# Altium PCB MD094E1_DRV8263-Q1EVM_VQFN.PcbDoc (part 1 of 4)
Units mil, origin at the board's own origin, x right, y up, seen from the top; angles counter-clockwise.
Board outline 3224.41 x 4078.74 mil, 4 copper layers (Top Layer, Signal Layer 1, Signal Layer 2, Bottom Layer), stack 61.2 mil thick; 223 components, 125 nets, 631 pads, 683 vias.
Unrouted connection lines stored in the file: 74.
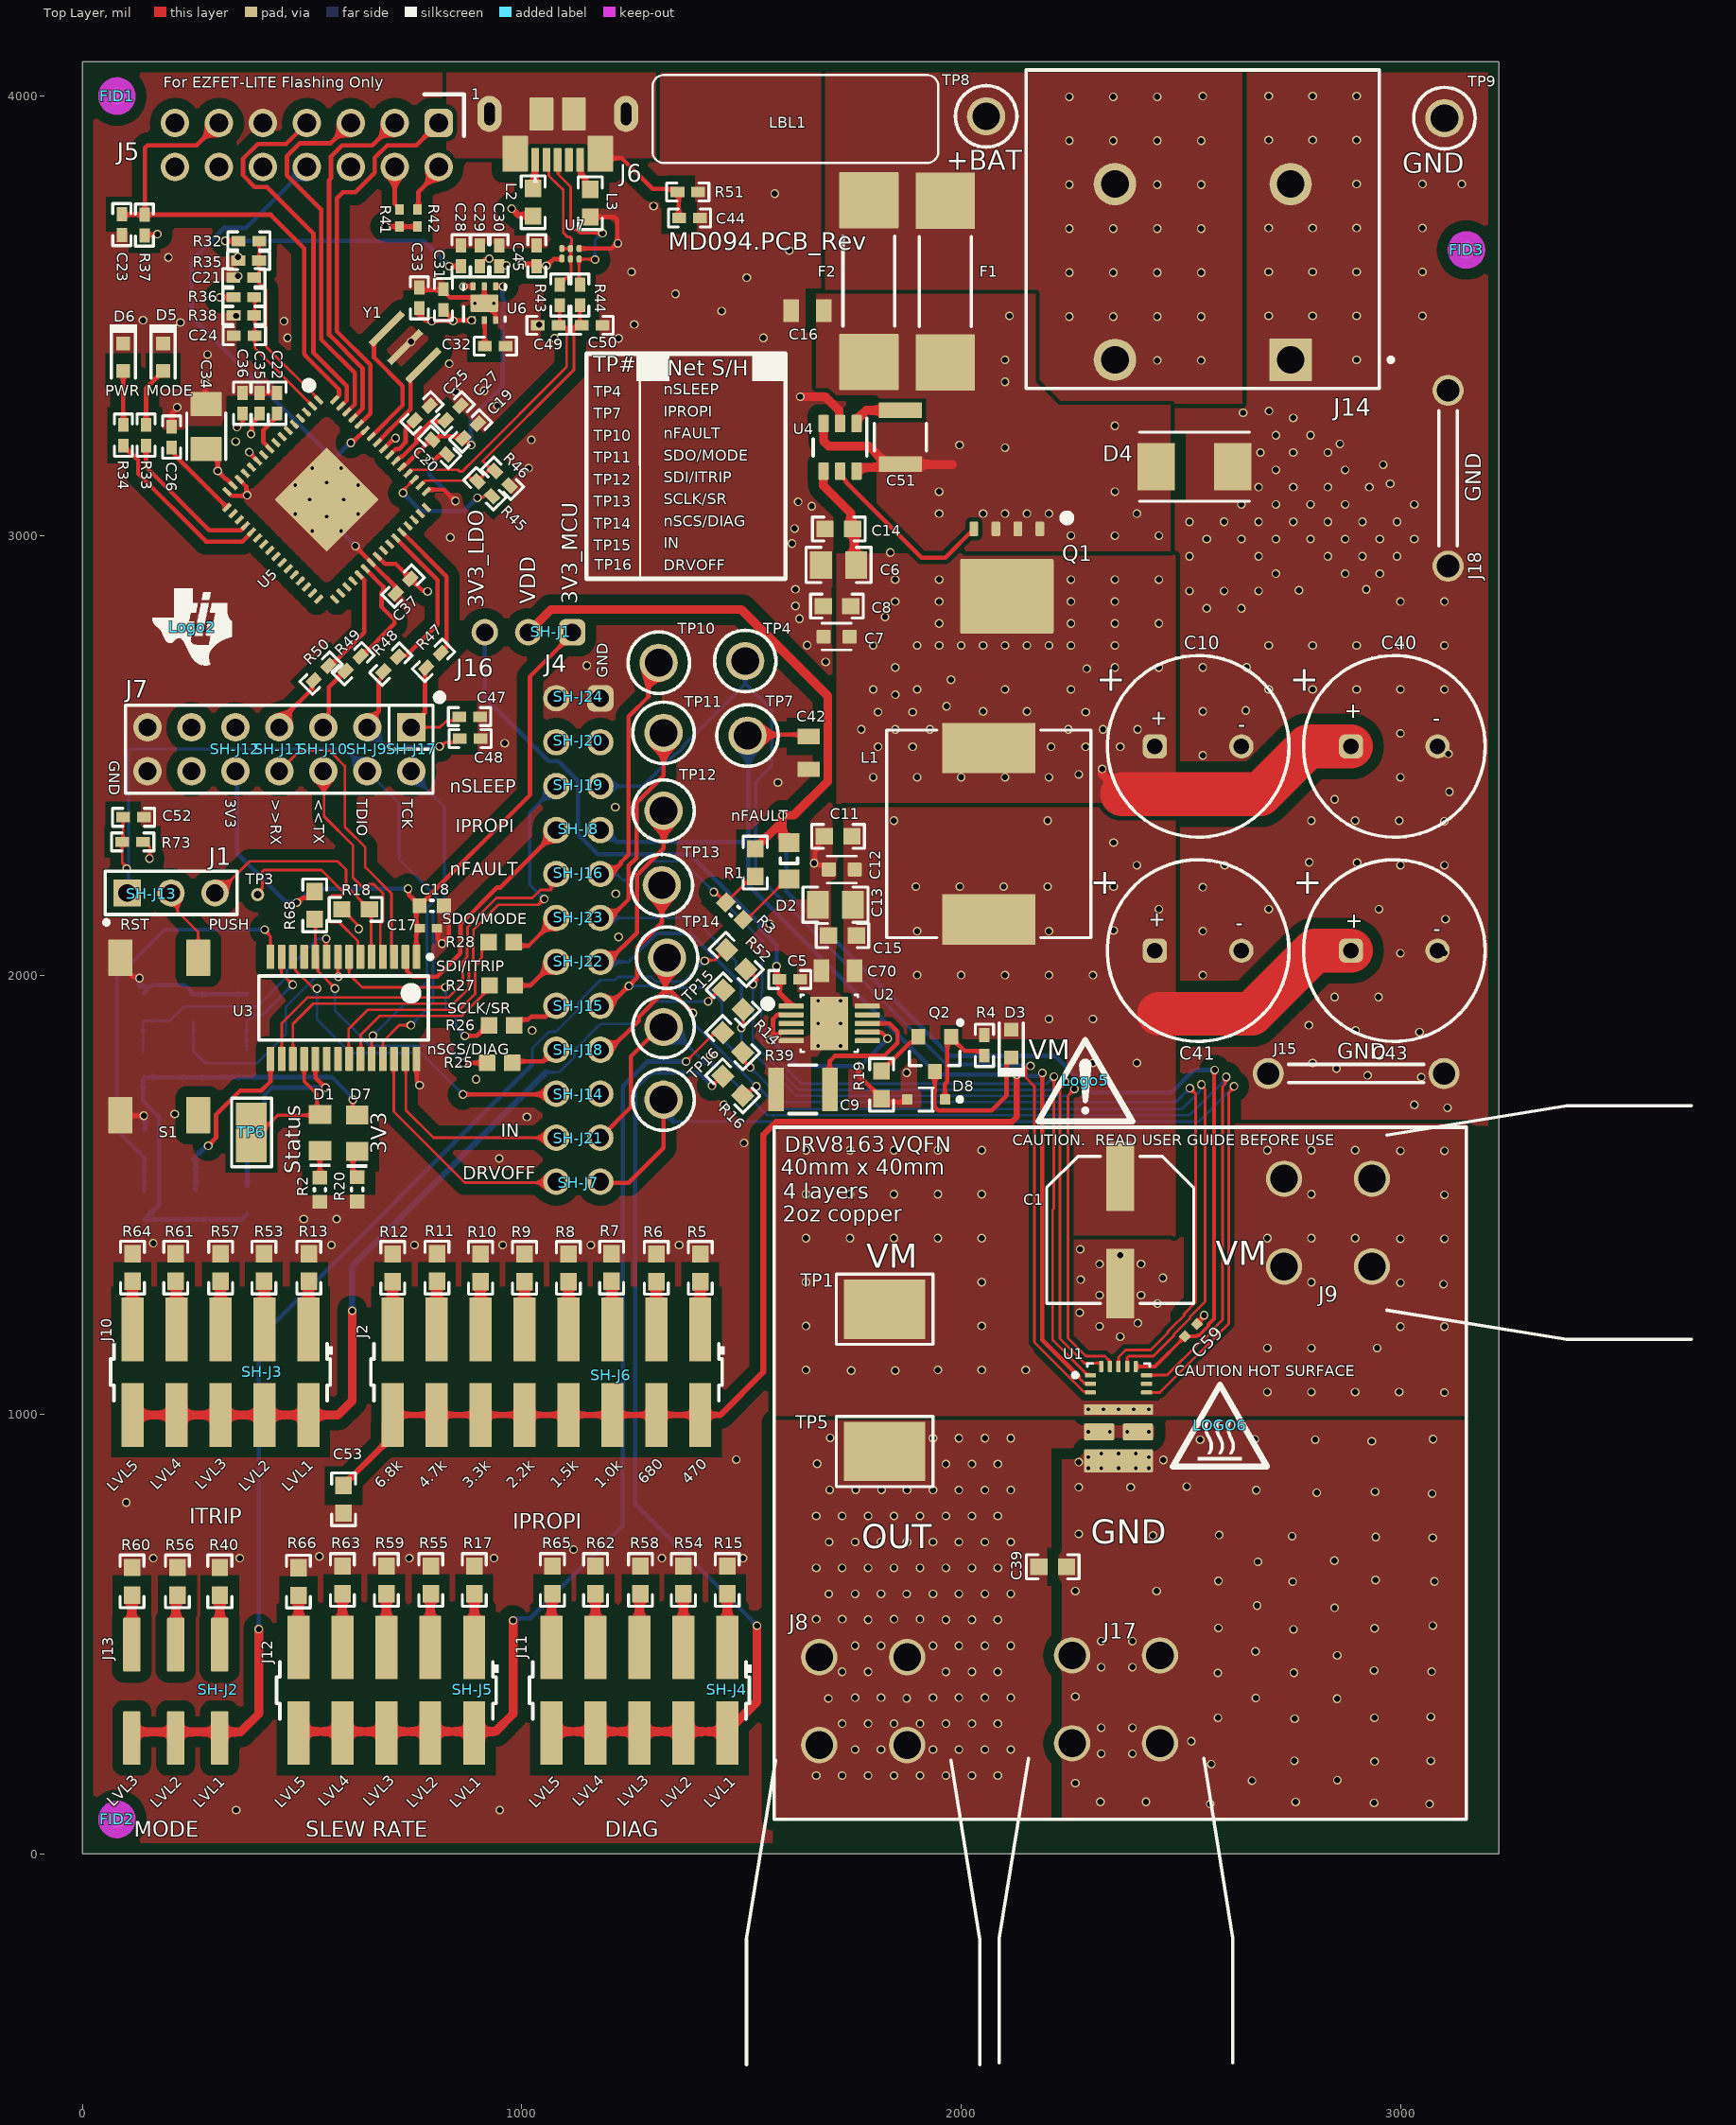
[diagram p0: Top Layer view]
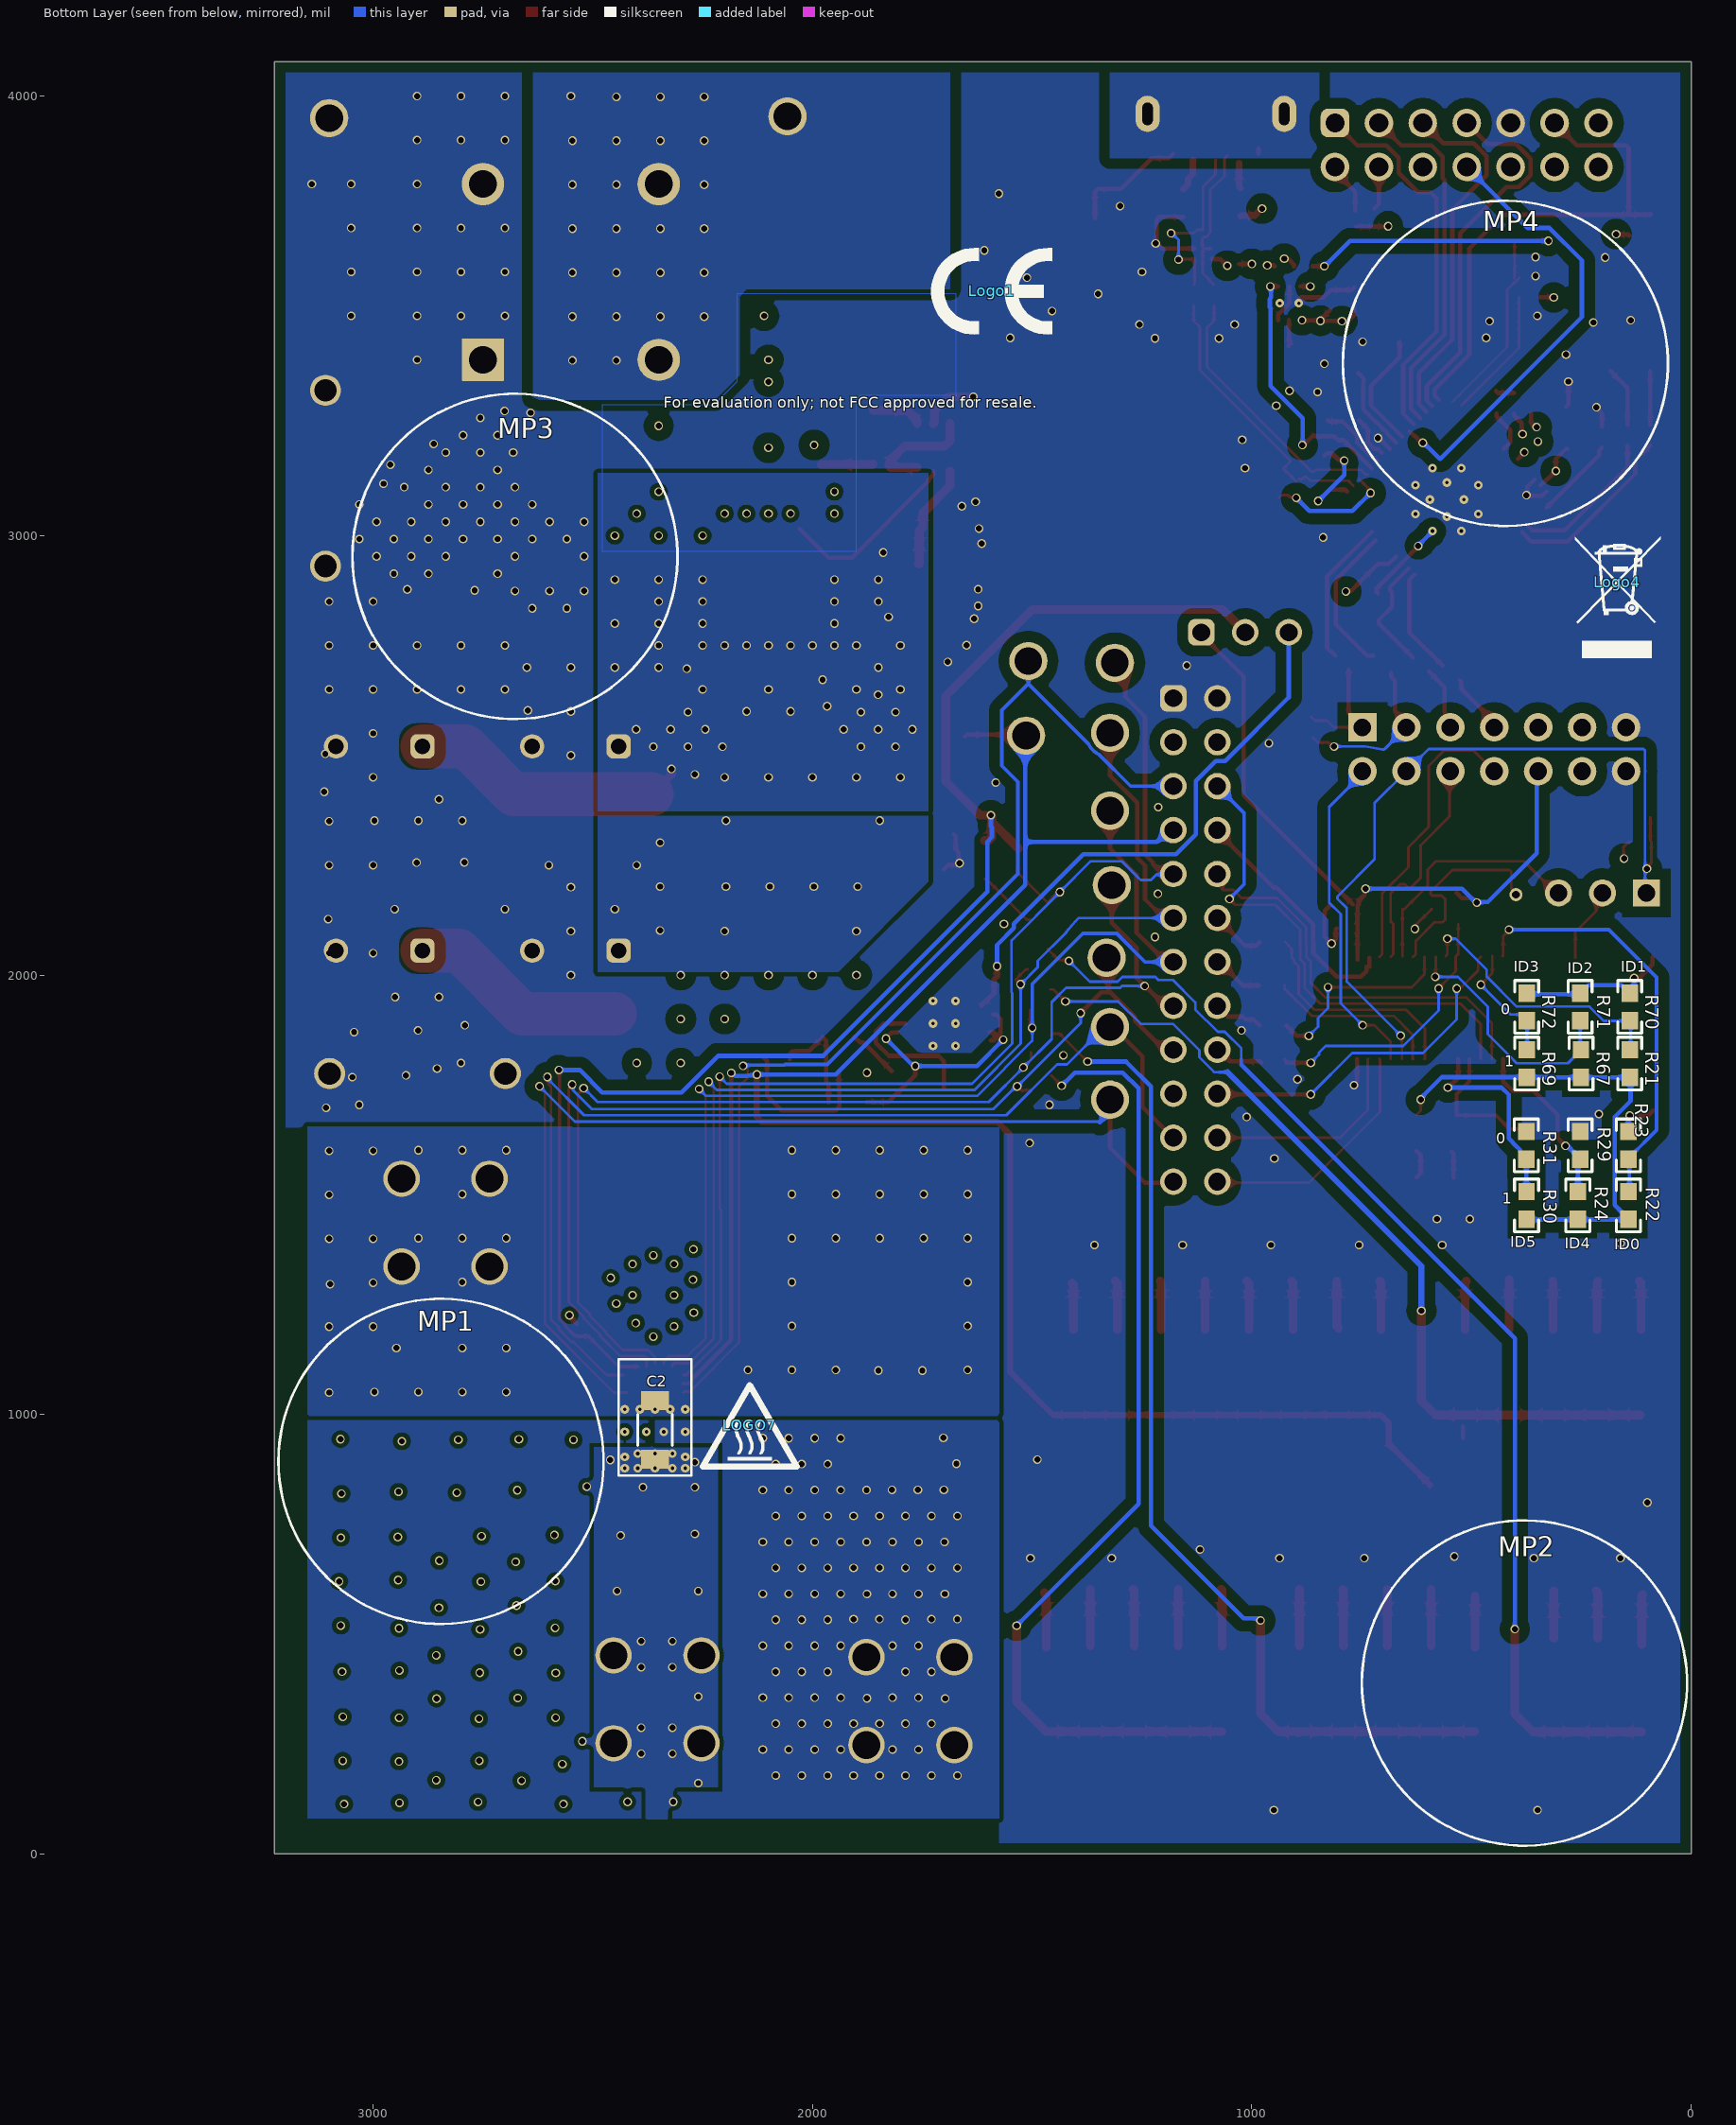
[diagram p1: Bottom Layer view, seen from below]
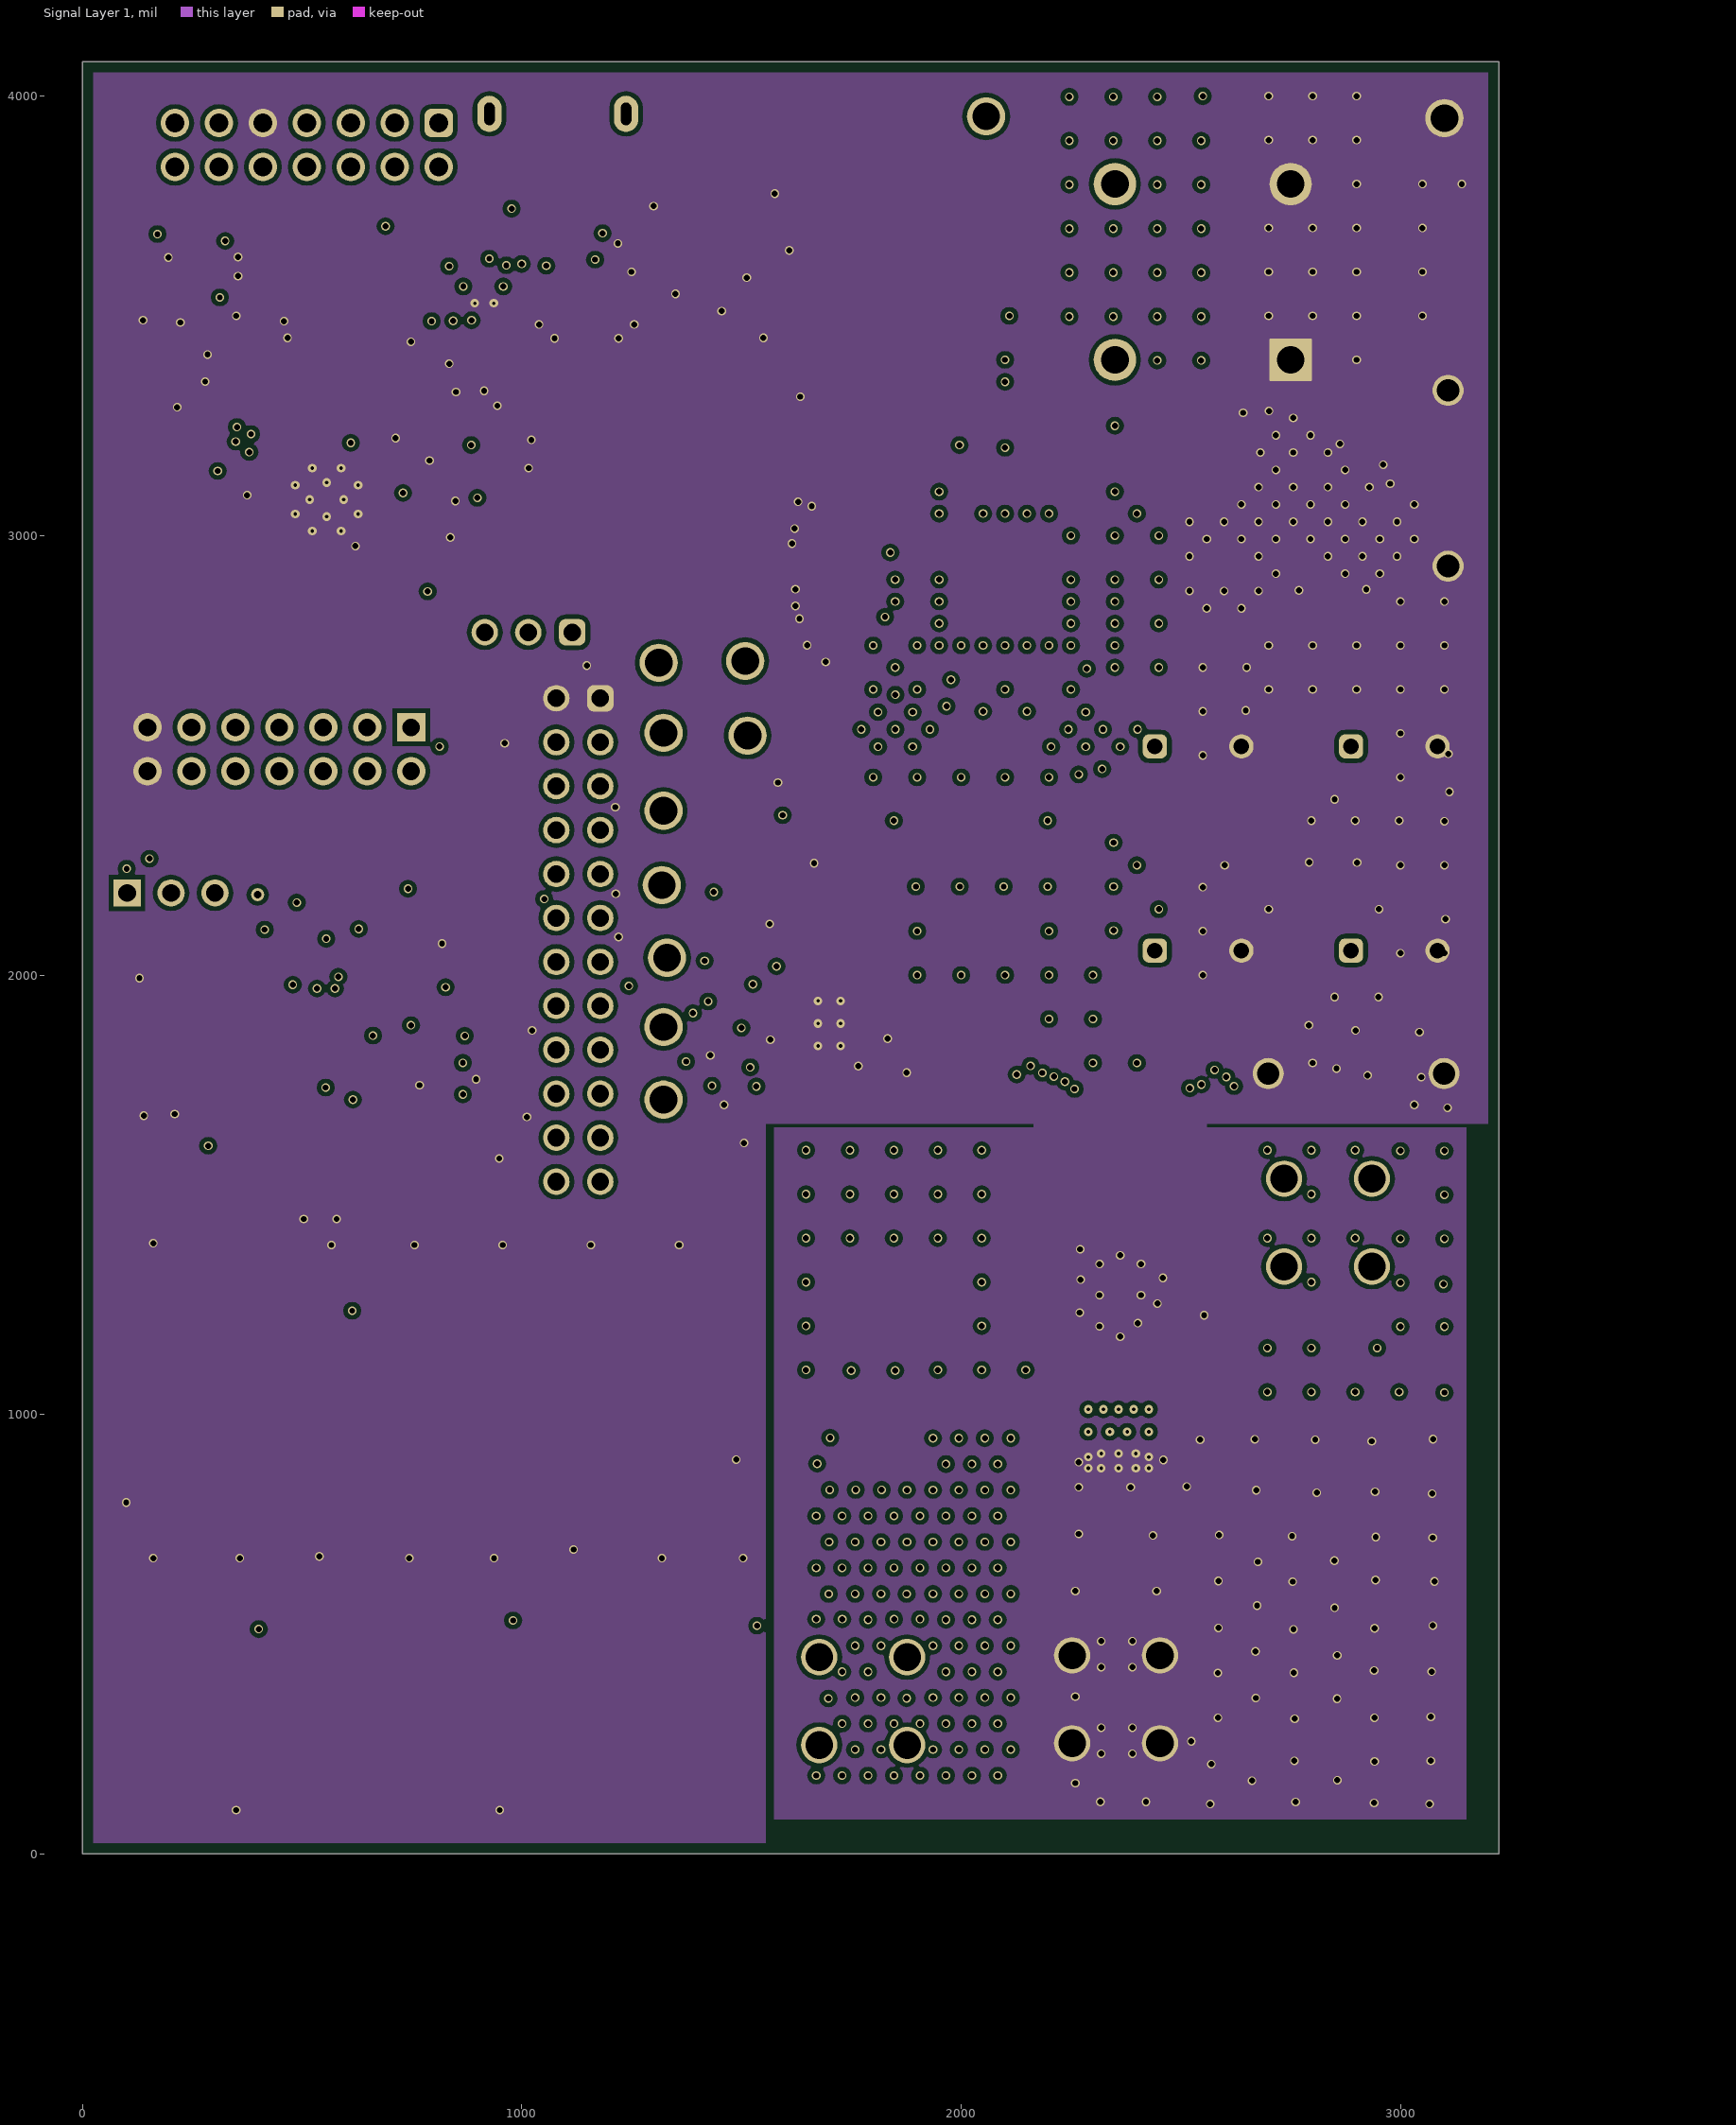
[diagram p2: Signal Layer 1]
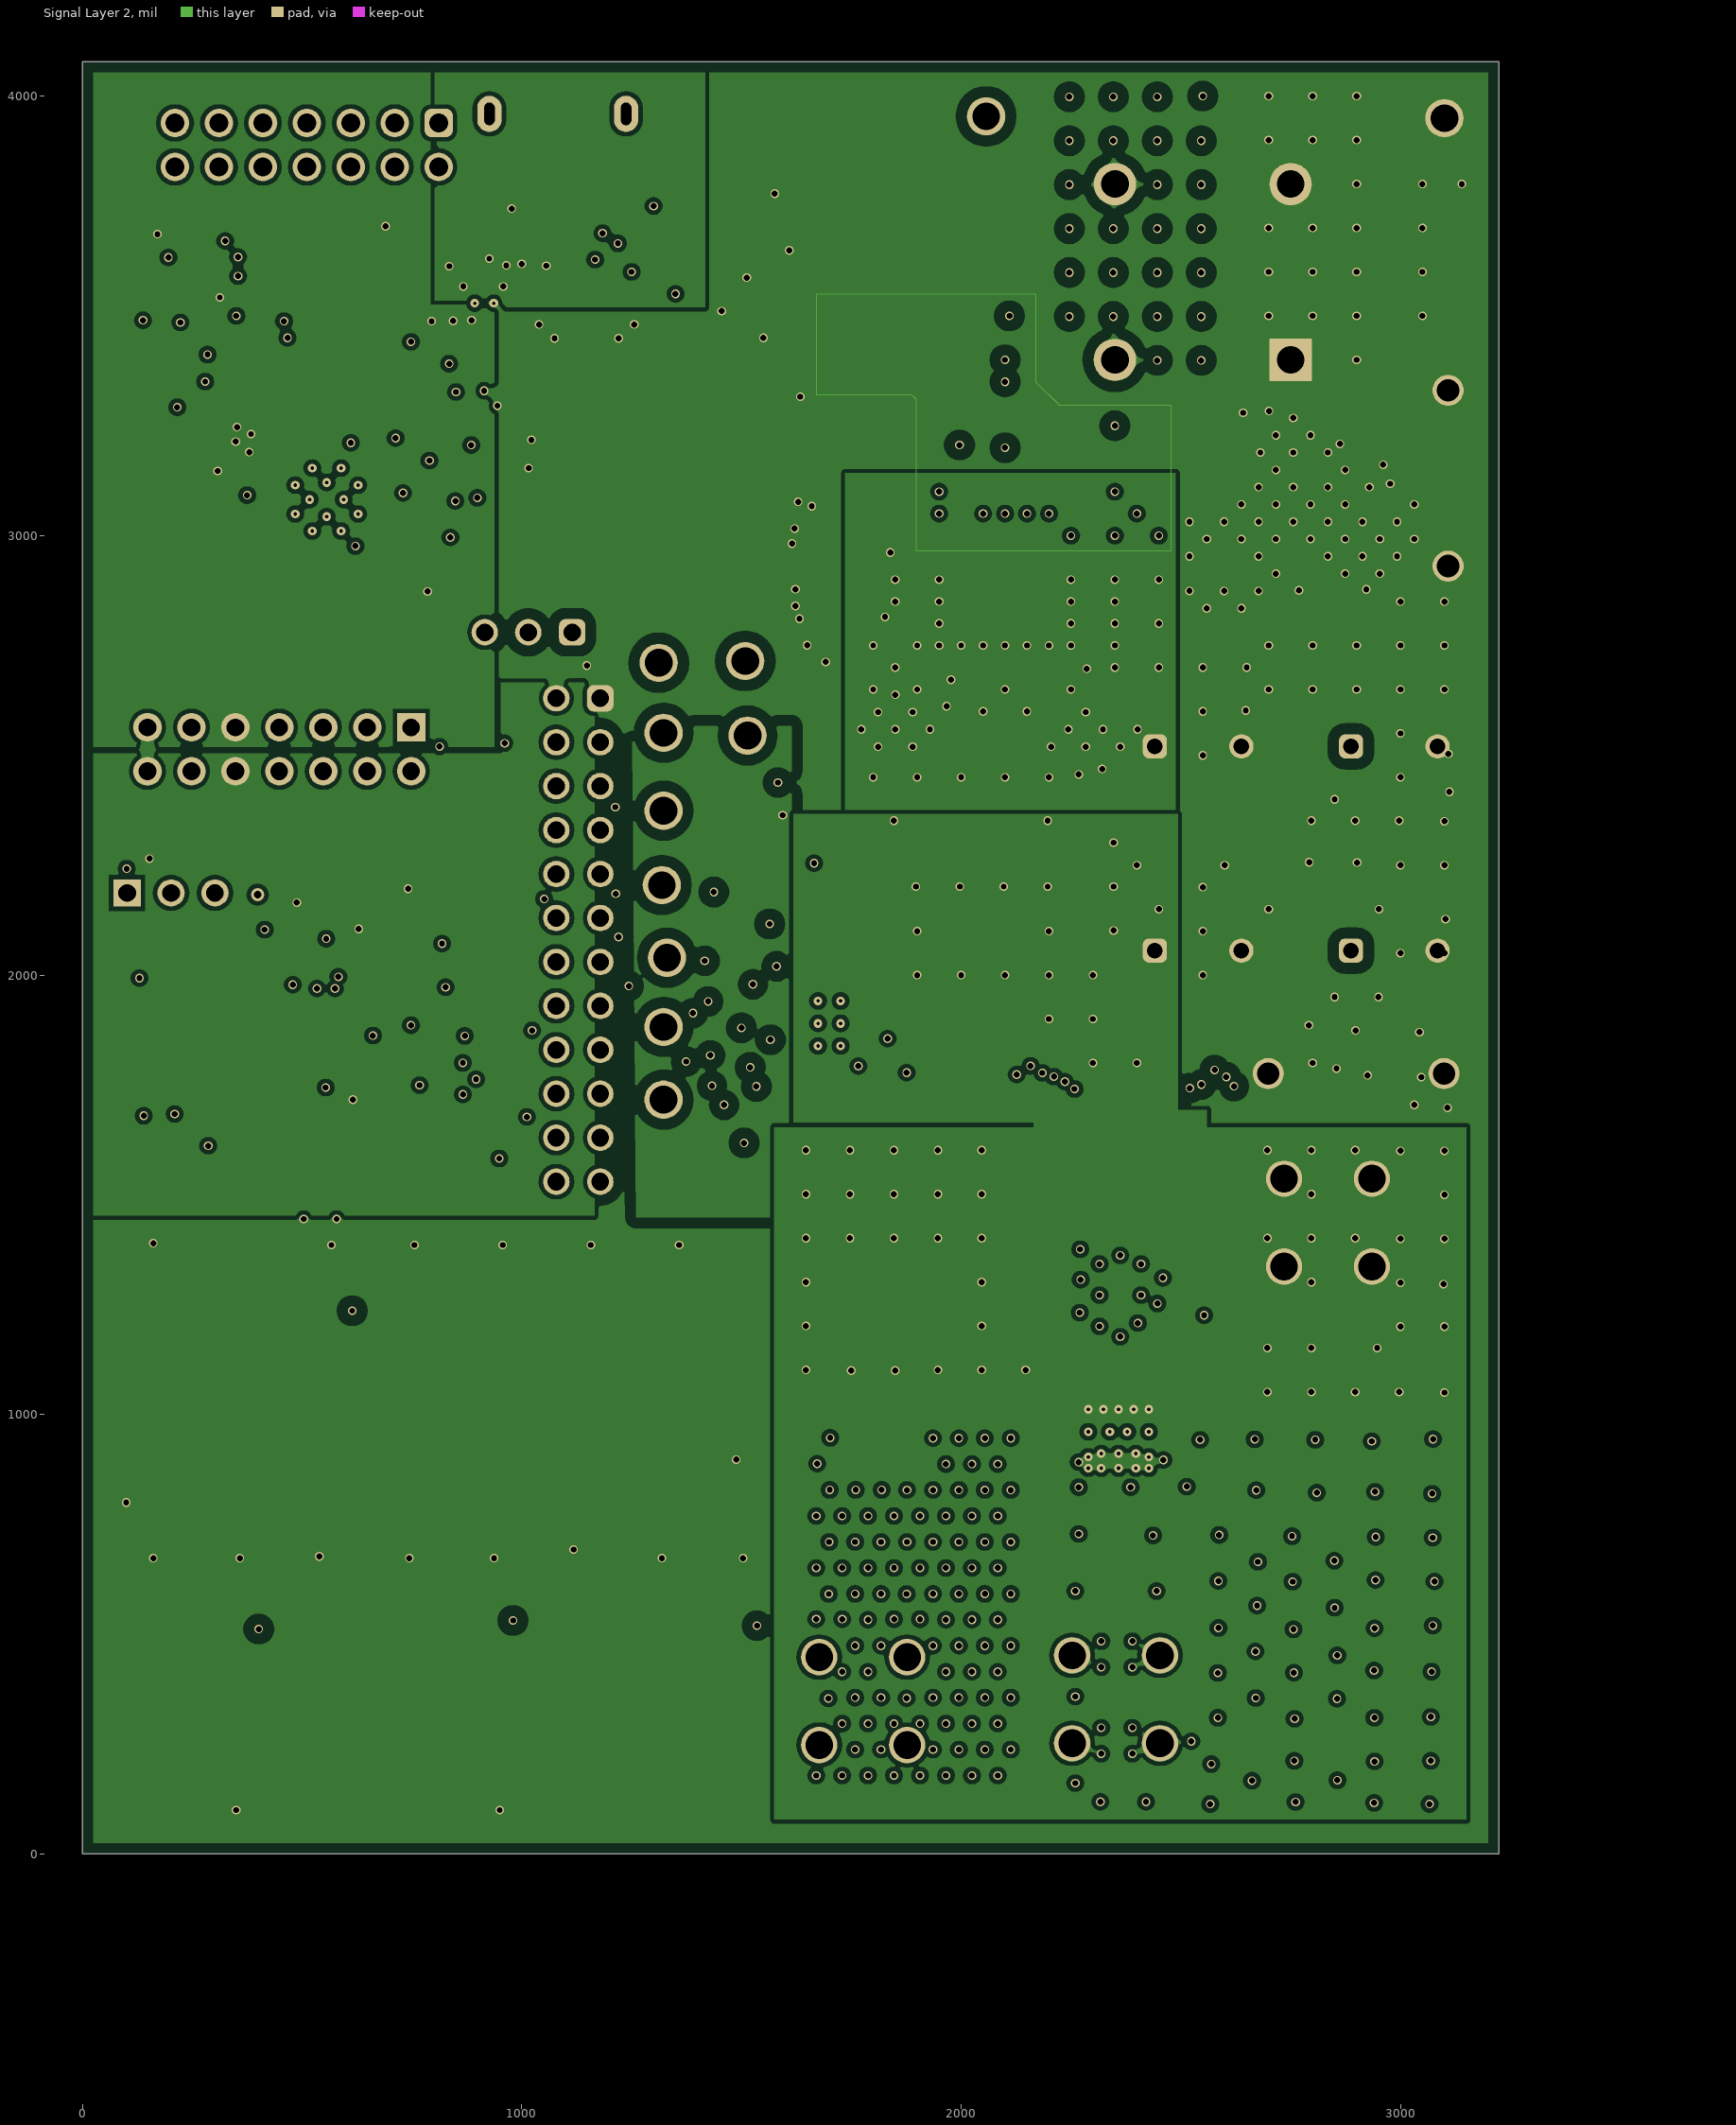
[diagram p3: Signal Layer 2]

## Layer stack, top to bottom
Top Solder: solder mask 0.4, Solder Resist, Dk 3.5
Top Layer: signal copper 2.8
Dielectric 1: prepreg 11.4, FR4 370, Dk 4.2
Signal Layer 1: signal copper 1.4
Dielectric 2: core 30, FR4 370, Dk 4.2
Signal Layer 2: signal copper 1.4
Dielectric 3: prepreg 11.4, FR4 370, Dk 4.2
Bottom Layer: signal copper 2.8
Bottom Solder: solder mask 0.4, Solder Resist, Dk 3.5

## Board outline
0,0 3224.41,0 3224.41,4078.74 0,4078.74

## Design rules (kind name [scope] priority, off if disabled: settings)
AcuteAngle [All] p1: minimum=4.50000000000000E+0001 checktracksonly=FALSE
AssemblyTestPointUsage [All] p1: valid=2
BoardOutlineClearance BoardOutlineClearance_MountingHoles [OnCopper and InComponentClass('Mounting Holes')] p1: gap=39.37 ignorepadtopadclearanceinfootprint=FALSE
BoardOutlineClearance BoardOutlineClearance_Poly [OnCopper and IsPoly] p2: gap=25 ignorepadtopadclearanceinfootprint=FALSE
BoardOutlineClearance [OnCopper and Not InComponentClass('Logo') and not InComponentClass('FiducialMark') and not InRegion(1000,500,4000,800) and not InPoly] p3: gap=75 ignorepadtopadclearanceinfootprint=FALSE
Clearance Clearance_89 [InNamedPolygon('TOP_LAYER_OUT1_P119')] p1: gap=10 ignorepadtopadclearanceinfootprint=TRUE except(0: Arc-Hole Track-Hole SMDPad-Hole THPad-Hole Via-Hole Fill-Hole Poly-Hole Region-Hole Text-Hole)
Clearance Clearance_88 [InNamedPolygon('TOP_LAYER_NONET_P-001')] p2: gap=10 ignorepadtopadclearanceinfootprint=TRUE except(0: Arc-Hole Track-Hole SMDPad-Hole THPad-Hole Via-Hole Fill-Hole Poly-Hole Region-Hole Text-Hole)
Clearance Clearance_87 [InNamedPolygon('TOP_LAYER_NONET_P-001')] p3: gap=10 ignorepadtopadclearanceinfootprint=TRUE except(0: Arc-Hole Track-Hole SMDPad-Hole THPad-Hole Via-Hole Fill-Hole Poly-Hole Region-Hole Text-Hole)
Clearance Clearance_86 [InNamedPolygon('TOP_LAYER_GND_P227')] p4: gap=10 ignorepadtopadclearanceinfootprint=TRUE except(0: Arc-Hole Track-Hole SMDPad-Hole THPad-Hole Via-Hole Fill-Hole Poly-Hole Region-Hole Text-Hole)
Clearance Clearance_85 [InNamedPolygon('TOP_LAYER_VM_P229')] p5: gap=10 ignorepadtopadclearanceinfootprint=TRUE except(0: Arc-Hole Track-Hole SMDPad-Hole THPad-Hole Via-Hole Fill-Hole Poly-Hole Region-Hole Text-Hole)
Clearance Clearance_84 [InNamedPolygon('TOP_LAYER_GND_P129')] p6: gap=10 ignorepadtopadclearanceinfootprint=TRUE except(0: Arc-Hole Track-Hole SMDPad-Hole THPad-Hole Via-Hole Fill-Hole Poly-Hole Region-Hole Text-Hole)
Clearance Clearance_83 [InNamedPolygon('TOP_LAYER_OUT1_P221')] p7: gap=3.94 ignorepadtopadclearanceinfootprint=TRUE except(0: Arc-Hole Track-Hole SMDPad-Hole THPad-Hole Via-Hole Fill-Hole Poly-Hole Region-Hole Text-Hole)
Clearance Clearance_82 [InNamedPolygon('TOP_LAYER_OUT1_P119')] p8: gap=10 ignorepadtopadclearanceinfootprint=TRUE except(0: Arc-Hole Track-Hole SMDPad-Hole THPad-Hole Via-Hole Fill-Hole Poly-Hole Region-Hole Text-Hole)
Clearance Clearance_81 [InNamedPolygon('TOP_LAYER_OUT1_P119')] p9: gap=10 ignorepadtopadclearanceinfootprint=TRUE except(0: Arc-Hole Track-Hole SMDPad-Hole THPad-Hole Via-Hole Fill-Hole Poly-Hole Region-Hole Text-Hole)
Clearance Clearance_80 [InNamedPolygon('TOP_LAYER_OUT1_P119')] p10: gap=10 ignorepadtopadclearanceinfootprint=TRUE except(0: Arc-Hole Track-Hole SMDPad-Hole THPad-Hole Via-Hole Fill-Hole Poly-Hole Region-Hole Text-Hole)
Clearance Clearance_79 [InNamedPolygon('TOP_LAYER_OUT1_P221')] p11: gap=10 ignorepadtopadclearanceinfootprint=TRUE except(0: Arc-Hole Track-Hole SMDPad-Hole THPad-Hole Via-Hole Fill-Hole Poly-Hole Region-Hole Text-Hole)
Clearance Clearance_78 [InNamedPolygon('TOP_LAYER_GND_P129')] p12: gap=10 ignorepadtopadclearanceinfootprint=TRUE except(0: Arc-Hole Track-Hole SMDPad-Hole THPad-Hole Via-Hole Fill-Hole Poly-Hole Region-Hole Text-Hole)
Clearance Clearance_77 [InNamedPolygon('TOP_LAYER_OUT2_P125')] p13: gap=10 ignorepadtopadclearanceinfootprint=TRUE except(0: Arc-Hole Track-Hole SMDPad-Hole THPad-Hole Via-Hole Fill-Hole Poly-Hole Region-Hole Text-Hole)
Clearance Clearance_76 [InNamedPolygon('TOP_LAYER_OUT1_P119')] p14: gap=10 ignorepadtopadclearanceinfootprint=TRUE except(0: Arc-Hole Track-Hole SMDPad-Hole THPad-Hole Via-Hole Fill-Hole Poly-Hole Region-Hole Text-Hole)
Clearance Clearance_75 [InNamedPolygon('TOP_LAYER_VM_P085')] p15: gap=10 ignorepadtopadclearanceinfootprint=TRUE except(0: Arc-Hole Track-Hole SMDPad-Hole THPad-Hole Via-Hole Fill-Hole Poly-Hole Region-Hole Text-Hole)
Clearance Clearance_74 [InNamedPolygon('TOP_LAYER_GND_P121')] p16: gap=10 ignorepadtopadclearanceinfootprint=TRUE except(0: Arc-Hole Track-Hole SMDPad-Hole THPad-Hole Via-Hole Fill-Hole Poly-Hole Region-Hole Text-Hole)
Clearance Clearance_73 [InNamedPolygon('TOP_LAYER_OUT2_P125') Or  InNamedPolygon('TOP_LAYER_OUT1_P119')] p17: gap=1.97 ignorepadtopadclearanceinfootprint=TRUE except(0: Arc-Hole Track-Hole SMDPad-Hole THPad-Hole Via-Hole Fill-Hole Poly-Hole Region-Hole Text-Hole)
Clearance Clearance_72 [InNamedPolygon('TOP_LAYER_OUT1_P119') Or  InNamedPolygon('TOP_LAYER_OUT2_P125')] p18: gap=3.94 ignorepadtopadclearanceinfootprint=TRUE except(0: Arc-Hole Track-Hole SMDPad-Hole THPad-Hole Via-Hole Fill-Hole Poly-Hole Region-Hole Text-Hole)
Clearance Clearance_71 [InNamedPolygon('TOP_LAYER_OUT1_P119')] p19: gap=10 ignorepadtopadclearanceinfootprint=TRUE except(0: Arc-Hole Track-Hole SMDPad-Hole THPad-Hole Via-Hole Fill-Hole Poly-Hole Region-Hole Text-Hole)
Clearance Clearance_70 [InNamedPolygon('TOP_LAYER_OUT2_P125')] p20: gap=10 ignorepadtopadclearanceinfootprint=TRUE except(0: Arc-Hole Track-Hole SMDPad-Hole THPad-Hole Via-Hole Fill-Hole Poly-Hole Region-Hole Text-Hole)
Clearance Clearance_69 [InNamedPolygon('TOP_LAYER_OUT1_P119')] p21: gap=3.94 ignorepadtopadclearanceinfootprint=TRUE except(0: Arc-Hole Track-Hole SMDPad-Hole THPad-Hole Via-Hole Fill-Hole Poly-Hole Region-Hole Text-Hole)
Clearance Clearance_68 [InNamedPolygon('TOP_LAYER_OUT2_P125')] p22: gap=3.94 ignorepadtopadclearanceinfootprint=TRUE except(0: Arc-Hole Track-Hole SMDPad-Hole THPad-Hole Via-Hole Fill-Hole Poly-Hole Region-Hole Text-Hole)
Clearance Clearance_67 [InNamedPolygon('TOP_LAYER_VM_P085')] p23: gap=3.94 ignorepadtopadclearanceinfootprint=TRUE except(0: Arc-Hole Track-Hole SMDPad-Hole THPad-Hole Via-Hole Fill-Hole Poly-Hole Region-Hole Text-Hole)
Clearance Clearance_66 [InNamedPolygon('BOTTOM_LAYER_P_IN_P174')] p24: gap=10 ignorepadtopadclearanceinfootprint=TRUE except(0: Arc-Hole Track-Hole SMDPad-Hole THPad-Hole Via-Hole Fill-Hole Poly-Hole Region-Hole Text-Hole)
Clearance Clearance_65 [InNamedPolygon('BOTTOM_LAYER_NETF1_2_P203')] p25: gap=10 ignorepadtopadclearanceinfootprint=TRUE except(0: Arc-Hole Track-Hole SMDPad-Hole THPad-Hole Via-Hole Fill-Hole Poly-Hole Region-Hole Text-Hole)
Clearance Clearance_64 [InNamedPolygon('BOTTOM_LAYER_VBAT_P080')] p26: gap=10 ignorepadtopadclearanceinfootprint=TRUE except(0: Arc-Hole Track-Hole SMDPad-Hole THPad-Hole Via-Hole Fill-Hole Poly-Hole Region-Hole Text-Hole)
Clearance Clearance_63 [InNamedPolygon('TOP_LAYER_VM_P167')] p27: gap=10 ignorepadtopadclearanceinfootprint=TRUE except(0: Arc-Hole Track-Hole SMDPad-Hole THPad-Hole Via-Hole Fill-Hole Poly-Hole Region-Hole Text-Hole)
Clearance Clearance_62 [InNamedPolygon('TOP_LAYER_VM_P167')] p28: gap=10 ignorepadtopadclearanceinfootprint=TRUE except(0: Arc-Hole Track-Hole SMDPad-Hole THPad-Hole Via-Hole Fill-Hole Poly-Hole Region-Hole Text-Hole)
Clearance Clearance_61 [InNamedPolygon('TOP_LAYER_VM_P171')] p29: gap=10 ignorepadtopadclearanceinfootprint=TRUE except(0: Arc-Hole Track-Hole SMDPad-Hole THPad-Hole Via-Hole Fill-Hole Poly-Hole Region-Hole Text-Hole)
Clearance Clearance_60 [InNamedPolygon('SIGNAL_LAYER_2_NETF1_2_P196')] p30: gap=10 ignorepadtopadclearanceinfootprint=TRUE except(0: Arc-Hole Track-Hole SMDPad-Hole THPad-Hole Via-Hole Fill-Hole Poly-Hole Region-Hole Text-Hole)
Clearance Clearance_59 [InNamedPolygon('SIGNAL_LAYER_2_VBAT_P197')] p31: gap=10 ignorepadtopadclearanceinfootprint=TRUE except(0: Arc-Hole Track-Hole SMDPad-Hole THPad-Hole Via-Hole Fill-Hole Poly-Hole Region-Hole Text-Hole)
Clearance Clearance_58 [InNamedPolygon('SIGNAL_LAYER_2_P_IN_P198')] p32: gap=10 ignorepadtopadclearanceinfootprint=TRUE except(0: Arc-Hole Track-Hole SMDPad-Hole THPad-Hole Via-Hole Fill-Hole Poly-Hole Region-Hole Text-Hole)
Clearance Clearance_57 [InNamedPolygon('SIGNAL_LAYER_2_3V3_P194')] p33: gap=10 ignorepadtopadclearanceinfootprint=TRUE except(0: Arc-Hole Track-Hole SMDPad-Hole THPad-Hole Via-Hole Fill-Hole Poly-Hole Region-Hole Text-Hole)
Clearance Clearance_56 [InNamedPolygon('TOP_LAYER_NETF1_2_P223')] p34: gap=10 ignorepadtopadclearanceinfootprint=TRUE except(0: Arc-Hole Track-Hole SMDPad-Hole THPad-Hole Via-Hole Fill-Hole Poly-Hole Region-Hole Text-Hole)
Clearance Clearance_55 [InNamedPolygon('TOP_LAYER_VBAT_P201')] p35: gap=10 ignorepadtopadclearanceinfootprint=TRUE except(0: Arc-Hole Track-Hole SMDPad-Hole THPad-Hole Via-Hole Fill-Hole Poly-Hole Region-Hole Text-Hole)
Clearance Clearance_54 [InNamedPolygon('TOP_LAYER_P_IN_P207')] p36: gap=10 ignorepadtopadclearanceinfootprint=TRUE except(0: Arc-Hole Track-Hole SMDPad-Hole THPad-Hole Via-Hole Fill-Hole Poly-Hole Region-Hole Text-Hole)
Clearance Clearance_53 [InNamedPolygon('TOP_LAYER_GND_P129')] p37: gap=10 ignorepadtopadclearanceinfootprint=TRUE except(0: Arc-Hole Track-Hole SMDPad-Hole THPad-Hole Via-Hole Fill-Hole Poly-Hole Region-Hole Text-Hole)
Clearance Clearance_52 [InNamedPolygon('SIGNAL_LAYER_2_VM_P177') Or  InNamedPolygon('SIGNAL_LAYER_2_VM_P179') Or  InNamedPolygon('SIGNAL_LAYER_2_VM_P160') Or  InNamedPolygon('SIGNAL_LAYER_2_VM_P175') Or  InNamedPolygon('SIGNAL_LAYER_2_VM_P181')] p38: gap=10 ignorepadtopadclearanceinfootprint=TRUE except(0: Arc-Hole Track-Hole SMDPad-Hole THPad-Hole Via-Hole Fill-Hole Poly-Hole Region-Hole Text-Hole)
Clearance Clearance_51 [InNamedPolygon('SIGNAL_LAYER_2_EZFET_VBUS_P136')] p39: gap=10 ignorepadtopadclearanceinfootprint=TRUE except(0: Arc-Hole Track-Hole SMDPad-Hole THPad-Hole Via-Hole Fill-Hole Poly-Hole Region-Hole Text-Hole)
Clearance Clearance_50 [InNamedPolygon('SIGNAL_LAYER_2_EZFET_VCC_P132')] p40: gap=10 ignorepadtopadclearanceinfootprint=TRUE except(0: Arc-Hole Track-Hole SMDPad-Hole THPad-Hole Via-Hole Fill-Hole Poly-Hole Region-Hole Text-Hole)
Clearance Clearance_49 [InNamedPolygon('SIGNAL_LAYER_2_3V3_MCU_P192')] p41: gap=10 ignorepadtopadclearanceinfootprint=TRUE except(0: Arc-Hole Track-Hole SMDPad-Hole THPad-Hole Via-Hole Fill-Hole Poly-Hole Region-Hole Text-Hole)
Clearance Clearance_48 [InNamedPolygon('SIGNAL_LAYER_1_GND_P190')] p42: gap=10 ignorepadtopadclearanceinfootprint=TRUE except(0: Arc-Hole Track-Hole SMDPad-Hole THPad-Hole Via-Hole Fill-Hole Poly-Hole Region-Hole Text-Hole)
Clearance Clearance_47 [InNamedPolygon('SIGNAL_LAYER_1_GND_P184')] p43: gap=10 ignorepadtopadclearanceinfootprint=TRUE except(0: Arc-Hole Track-Hole SMDPad-Hole THPad-Hole Via-Hole Fill-Hole Poly-Hole Region-Hole Text-Hole)
Clearance Clearance_46 [InNamedPolygon('BOTTOM_LAYER_GND_P231')] p44: gap=10 ignorepadtopadclearanceinfootprint=TRUE except(0: Arc-Hole Track-Hole SMDPad-Hole THPad-Hole Via-Hole Fill-Hole Poly-Hole Region-Hole Text-Hole)
Clearance Clearance_45 [InNamedPolygon('BOTTOM_LAYER_GND_P231')] p45: gap=10 ignorepadtopadclearanceinfootprint=TRUE except(0: Arc-Hole Track-Hole SMDPad-Hole THPad-Hole Via-Hole Fill-Hole Poly-Hole Region-Hole Text-Hole)
Clearance Clearance_44 [InNamedPolygon('BOTTOM_LAYER_OUT2_P163')] p46: gap=10 ignorepadtopadclearanceinfootprint=TRUE except(0: Arc-Hole Track-Hole SMDPad-Hole THPad-Hole Via-Hole Fill-Hole Poly-Hole Region-Hole Text-Hole)
Clearance Clearance_43 [InNamedPolygon('BOTTOM_LAYER_VM_P166')] p47: gap=10 ignorepadtopadclearanceinfootprint=TRUE except(0: Arc-Hole Track-Hole SMDPad-Hole THPad-Hole Via-Hole Fill-Hole Poly-Hole Region-Hole Text-Hole)
Clearance Clearance_42 [InNamedPolygon('BOTTOM_LAYER_VM_P219')] p48: gap=10 ignorepadtopadclearanceinfootprint=TRUE except(0: Arc-Hole Track-Hole SMDPad-Hole THPad-Hole Via-Hole Fill-Hole Poly-Hole Region-Hole Text-Hole)
Clearance Clearance_41 [InNamedPolygon('BOTTOM_LAYER_OUT1_P164')] p49: gap=10 ignorepadtopadclearanceinfootprint=TRUE except(0: Arc-Hole Track-Hole SMDPad-Hole THPad-Hole Via-Hole Fill-Hole Poly-Hole Region-Hole Text-Hole)
Clearance Clearance_40 [InNamedPolygon('BOTTOM_LAYER_GND_P162')] p50: gap=10 ignorepadtopadclearanceinfootprint=TRUE except(0: Arc-Hole Track-Hole SMDPad-Hole THPad-Hole Via-Hole Fill-Hole Poly-Hole Region-Hole Text-Hole)
Clearance Clearance_39 [InNamedPolygon('SIGNAL_LAYER_2_VM_P160')] p51: gap=10 ignorepadtopadclearanceinfootprint=TRUE except(0: Arc-Hole Track-Hole SMDPad-Hole THPad-Hole Via-Hole Fill-Hole Poly-Hole Region-Hole Text-Hole)
Clearance Clearance_38 [InNamedPolygon('SIGNAL_LAYER_2_NONET_P138')] p52: gap=10 ignorepadtopadclearanceinfootprint=TRUE except(0: Arc-Hole Track-Hole SMDPad-Hole THPad-Hole Via-Hole Fill-Hole Poly-Hole Region-Hole Text-Hole)
Clearance Clearance_37 [InNamedPolygon('SIGNAL_LAYER_1_VM_P146')] p53: gap=10 ignorepadtopadclearanceinfootprint=TRUE except(0: Arc-Hole Track-Hole SMDPad-Hole THPad-Hole Via-Hole Fill-Hole Poly-Hole Region-Hole Text-Hole)
Clearance Clearance_36 [InNamedPolygon('SIGNAL_LAYER_2_GND_P156')] p54: gap=10 ignorepadtopadclearanceinfootprint=TRUE except(0: Arc-Hole Track-Hole SMDPad-Hole THPad-Hole Via-Hole Fill-Hole Poly-Hole Region-Hole Text-Hole)
Clearance Clearance_35 [InNamedPolygon('SIGNAL_LAYER_1_VM_P148') Or  InNamedPolygon('SIGNAL_LAYER_1_VM_P148')] p55: gap=10 ignorepadtopadclearanceinfootprint=TRUE except(0: Arc-Hole Track-Hole SMDPad-Hole THPad-Hole Via-Hole Fill-Hole Poly-Hole Region-Hole Text-Hole)
Clearance Clearance_34 [InNamedPolygon('SIGNAL_LAYER_1_GND_P154')] p56: gap=10 ignorepadtopadclearanceinfootprint=TRUE except(0: Arc-Hole Track-Hole SMDPad-Hole THPad-Hole Via-Hole Fill-Hole Poly-Hole Region-Hole Text-Hole)
Clearance Clearance_33 [InNamedPolygon('SIGNAL_LAYER_2_NONET_P138')] p57: gap=10 ignorepadtopadclearanceinfootprint=TRUE except(0: Arc-Hole Track-Hole SMDPad-Hole THPad-Hole Via-Hole Fill-Hole Poly-Hole Region-Hole Text-Hole)
Clearance Clearance_32 [InNamedPolygon('SIGNAL_LAYER_2_GND_P082')] p58: gap=10 ignorepadtopadclearanceinfootprint=TRUE except(0: Arc-Hole Track-Hole SMDPad-Hole THPad-Hole Via-Hole Fill-Hole Poly-Hole Region-Hole Text-Hole)
Clearance Clearance_31 [InNamedPolygon('TOP_LAYER_GND_P076')] p59: gap=10 ignorepadtopadclearanceinfootprint=TRUE except(0: Arc-Hole Track-Hole SMDPad-Hole THPad-Hole Via-Hole Fill-Hole Poly-Hole Region-Hole Text-Hole)
Clearance Clearance_30 [InNamedPolygon('TOP_LAYER_GND_P087')] p60: gap=10 ignorepadtopadclearanceinfootprint=TRUE except(0: Arc-Hole Track-Hole SMDPad-Hole THPad-Hole Via-Hole Fill-Hole Poly-Hole Region-Hole Text-Hole)
Clearance Clearance_29 [InNamedPolygon('TOP_LAYER_VM_P127') Or  InNamedPolygon('TOP_LAYER_VM_P085')] p61: gap=10 ignorepadtopadclearanceinfootprint=TRUE except(0: Arc-Hole Track-Hole SMDPad-Hole THPad-Hole Via-Hole Fill-Hole Poly-Hole Region-Hole Text-Hole)
Clearance Clearance_28 [InNamedPolygon('TOP_LAYER_GND_P117')] p62: gap=10 ignorepadtopadclearanceinfootprint=TRUE except(0: Arc-Hole Track-Hole SMDPad-Hole THPad-Hole Via-Hole Fill-Hole Poly-Hole Region-Hole Text-Hole)
Clearance Clearance_27 [InNamedPolygon('TOP_LAYER_OUT2_P125') Or  InNamedPolygon('TOP_LAYER_OUT1_P119')] p63: gap=10 ignorepadtopadclearanceinfootprint=TRUE except(0: Arc-Hole Track-Hole SMDPad-Hole THPad-Hole Via-Hole Fill-Hole Poly-Hole Region-Hole Text-Hole)
Clearance Clearance_26 [InNamedPolygon('SIGNAL_LAYER_2_NONET_P113')] p64: gap=10 ignorepadtopadclearanceinfootprint=TRUE except(0: Arc-Hole Track-Hole SMDPad-Hole THPad-Hole Via-Hole Fill-Hole Poly-Hole Region-Hole Text-Hole)
Clearance Clearance_25 [InNamedPolygon('BOTTOM_LAYER_NONET_P115')] p65: gap=10 ignorepadtopadclearanceinfootprint=TRUE except(0: Arc-Hole Track-Hole SMDPad-Hole THPad-Hole Via-Hole Fill-Hole Poly-Hole Region-Hole Text-Hole)
Clearance Clearance_24 [InNamedPolygon('SIGNAL_LAYER_1_NONET_P111')] p66: gap=10 ignorepadtopadclearanceinfootprint=TRUE except(0: Arc-Hole Track-Hole SMDPad-Hole THPad-Hole Via-Hole Fill-Hole Poly-Hole Region-Hole Text-Hole)
Clearance Clearance_23 [InNamedPolygon('TOP_LAYER_NONET_P083')] p67: gap=10 ignorepadtopadclearanceinfootprint=TRUE except(0: Arc-Hole Track-Hole SMDPad-Hole THPad-Hole Via-Hole Fill-Hole Poly-Hole Region-Hole Text-Hole)
Clearance Clearance_22 [InNamedPolygon('TOP_LAYER_NONET_P105')] p68: gap=10 ignorepadtopadclearanceinfootprint=TRUE except(0: Arc-Hole Track-Hole SMDPad-Hole THPad-Hole Via-Hole Fill-Hole Poly-Hole Region-Hole Text-Hole)
Clearance Clearance_21 [InNamedPolygon('TOP_LAYER_OUT2_P107')] p69: gap=10 ignorepadtopadclearanceinfootprint=TRUE except(0: Arc-Hole Track-Hole SMDPad-Hole THPad-Hole Via-Hole Fill-Hole Poly-Hole Region-Hole Text-Hole)
Clearance Clearance_20 [InNamedPolygon('TOP_LAYER_NONET_P101')] p70: gap=10 ignorepadtopadclearanceinfootprint=TRUE except(0: Arc-Hole Track-Hole SMDPad-Hole THPad-Hole Via-Hole Fill-Hole Poly-Hole Region-Hole Text-Hole)
Clearance Clearance_19 [InNamedPolygon('TOP_LAYER_OUT1_P103')] p71: gap=10 ignorepadtopadclearanceinfootprint=TRUE except(0: Arc-Hole Track-Hole SMDPad-Hole THPad-Hole Via-Hole Fill-Hole Poly-Hole Region-Hole Text-Hole)
Clearance Clearance_18 [InNet('OUT1')] p72: gap=10 ignorepadtopadclearanceinfootprint=TRUE except(0: Arc-Hole Track-Hole SMDPad-Hole THPad-Hole Via-Hole Fill-Hole Poly-Hole Region-Hole Text-Hole)
Clearance Clearance_17 [InNamedPolygon('TOP_LAYER_OUT1_P000')] p73: gap=10 ignorepadtopadclearanceinfootprint=TRUE except(0: Arc-Hole Track-Hole SMDPad-Hole THPad-Hole Via-Hole Fill-Hole Poly-Hole Region-Hole Text-Hole)
Clearance Clearance_16 [InNamedPolygon('TOP_LAYER_OUT1_P000') vs InNet('OUT1')] p74: gap=3.94 ignorepadtopadclearanceinfootprint=TRUE except(0: Arc-Hole Track-Hole SMDPad-Hole THPad-Hole Via-Hole Fill-Hole Poly-Hole Region-Hole Text-Hole)
Clearance Clearance_15 [InNamedPolygon('TOP_LAYER_OUT1_P000')] p75: gap=3.94 ignorepadtopadclearanceinfootprint=TRUE except(0: Arc-Hole Track-Hole SMDPad-Hole THPad-Hole Via-Hole Fill-Hole Poly-Hole Region-Hole Text-Hole)
Clearance Clearance_14 [InNamedPolygon('TOP_LAYER_NONET_P093')] p76: gap=3.94 ignorepadtopadclearanceinfootprint=TRUE except(0: Arc-Hole Track-Hole SMDPad-Hole THPad-Hole Via-Hole Fill-Hole Poly-Hole Region-Hole Text-Hole)
Clearance Clearance_13 [InNamedPolygon('TOP_LAYER_NONET_P093')] p77: gap=10 ignorepadtopadclearanceinfootprint=TRUE except(0: Arc-Hole Track-Hole SMDPad-Hole THPad-Hole Via-Hole Fill-Hole Poly-Hole Region-Hole Text-Hole)
Clearance Clearance_12 [InNamedPolygon('TOP_LAYER_OUT2_P099')] p78: gap=10 ignorepadtopadclearanceinfootprint=TRUE except(0: Arc-Hole Track-Hole SMDPad-Hole THPad-Hole Via-Hole Fill-Hole Poly-Hole Region-Hole Text-Hole)
Clearance Clearance_11 [InNamedPolygon('TOP_LAYER_OUT2_P099')] p79: gap=10 ignorepadtopadclearanceinfootprint=TRUE except(0: Arc-Hole Track-Hole SMDPad-Hole THPad-Hole Via-Hole Fill-Hole Poly-Hole Region-Hole Text-Hole)
Clearance Clearance_10 [InNamedPolygon('TOP_LAYER_OUT1_P000')] p80: gap=10 ignorepadtopadclearanceinfootprint=TRUE except(0: Arc-Hole Track-Hole SMDPad-Hole THPad-Hole Via-Hole Fill-Hole Poly-Hole Region-Hole Text-Hole)
Clearance Clearance_9 [InNamedPolygon('TOP_LAYER_OUT1_P000')] p81: gap=10 ignorepadtopadclearanceinfootprint=TRUE except(0: Arc-Hole Track-Hole SMDPad-Hole THPad-Hole Via-Hole Fill-Hole Poly-Hole Region-Hole Text-Hole)
Clearance Clearance_8 [InNamedPolygon('BOTTOM_LAYER_NONET_P079') Or  InNamedPolygon('SIGNAL_LAYER_2_NONET_P078') Or  InNamedPolygon('SIGNAL_LAYER_1_NONET_P077') Or  InNamedPolygon('TOP_LAYER_NONET_P083') Or  InNamedPolygon('BOTTOM_LAYER_NONET_P072') Or  InNamedPolygon('SIGNAL_LAYER_2_NONET_P070') Or  InNamedPolygon('SIGNAL_LAYER_1_NONET_P059') Or  InNamedPolygon('TOP_LAYER_OUT2_P058') Or  InNamedPolygon('BOTTOM_LAYER_NONET_P056') Or  InNamedPolygon('SIGNAL_LAYER_2_NONET_P054') Or  InNamedPolygon('SIGNAL_LAYER_1_NONET_P052') Or  InNamedPolygon('TOP_LAYER_OUT1_P050') Or  InNamedPolygon('BOTTOM_LAYER_VM_P044') Or  InNamedPolygon('SIGNAL_LAYER_2_VM_P042') Or  InNamedPolygon('SIGNAL_LAYER_1_VM_P040') Or  InNamedPolygon('TOP_LAYER_VM_P038') Or  InNamedPolygon('BOTTOM_LAYER_VM_P036') Or  InNamedPolygon('SIGNAL_LAYER_2_VM_P018') Or  InNamedPolygon('SIGNAL_LAYER_1_VM_P016') Or  InNamedPolygon('TOP_LAYER_VM_P002')] p82: gap=10 ignorepadtopadclearanceinfootprint=TRUE except(0: Arc-Hole Track-Hole SMDPad-Hole THPad-Hole Via-Hole Fill-Hole Poly-Hole Region-Hole Text-Hole)
Clearance Clearance_7 [InNamedPolygon('TOP_LAYER_NONET_P089') Or  InNamedPolygon('TOP_LAYER_NONET_P090')] p83: gap=10 ignorepadtopadclearanceinfootprint=TRUE except(0: Arc-Hole Track-Hole SMDPad-Hole THPad-Hole Via-Hole Fill-Hole Poly-Hole Region-Hole Text-Hole)
Clearance Clearance_6 [InNamedPolygon('BOTTOM_LAYER_EZFET_USB_SHIELD_P002') Or  InNamedPolygon('TOP_LAYER_EZFET_USB_SHIELD_P173') Or  InNamedPolygon('SIGNAL_LAYER_2_EZFET_VBUS_P018') Or  InNamedPolygon('SIGNAL_LAYER_2_EZFET_VCC_P016')] p84: gap=10 ignorepadtopadclearanceinfootprint=TRUE except(0: Arc-Hole Track-Hole SMDPad-Hole THPad-Hole Via-Hole Fill-Hole Poly-Hole Region-Hole Text-Hole)
Clearance Clearance_5 [InNamedPolygon('TOP_LAYER_NONET_P072')] p85: gap=10 ignorepadtopadclearanceinfootprint=TRUE except(0: Arc-Hole Track-Hole SMDPad-Hole THPad-Hole Via-Hole Fill-Hole Poly-Hole Region-Hole Text-Hole)
Clearance Clearance_4 [InNamedPolygon('TOP_LAYER_VM_P123') Or  InNamedPolygon('TOP_LAYER_VM_P123') Or  InNamedPolygon('TOP_LAYER_VM_P123')] p86: gap=10 ignorepadtopadclearanceinfootprint=TRUE except(0: Arc-Hole Track-Hole SMDPad-Hole THPad-Hole Via-Hole Fill-Hole Poly-Hole Region-Hole Text-Hole)
Clearance Clearance_3 [InNamedPolygon('TOP_LAYER_VM_P042') Or  InNamedPolygon('TOP_LAYER_VM_P044') Or  InNamedPolygon('TOP_LAYER_OUT2_P040') Or  InNamedPolygon('TOP_LAYER_OUT1_P038')] p87: gap=10 ignorepadtopadclearanceinfootprint=TRUE except(0: Arc-Hole Track-Hole SMDPad-Hole THPad-Hole Via-Hole Fill-Hole Poly-Hole Region-Hole Text-Hole)
Clearance Clearance_2 [InNamedPolygon('TOP_LAYER_OUT2_P040')] p88: gap=10 ignorepadtopadclearanceinfootprint=TRUE except(0: Arc-Hole Track-Hole SMDPad-Hole THPad-Hole Via-Hole Fill-Hole Poly-Hole Region-Hole Text-Hole)
Clearance Clearance_1 [InNamedPolygon('TOP_LAYER_VM_P046')] p89: gap=5.98 ignorepadtopadclearanceinfootprint=TRUE except(0: Arc-Hole Track-Hole SMDPad-Hole THPad-Hole Via-Hole Fill-Hole Poly-Hole Region-Hole Text-Hole)
Clearance Clearance_Keepouts [((IsTrack Or IsArc) And Not InPoly) And IsFree and IsKeepOut vs ((IsTrack Or IsArc) And Not InPoly) And IsFree and IsKeepOut] p90: gap=0 ignorepadtopadclearanceinfootprint=FALSE
Clearance Clearance_Poly [InPolygon] p91: gap=25 ignorepadtopadclearanceinfootprint=TRUE
Clearance Clearance_FiducialMark [IsKeepOut and InComponentClass('FiducialMark') vs IsPad and InComponentClass('FiducialMark')] p92: gap=0 ignorepadtopadclearanceinfootprint=FALSE
Clearance [All] p93: gap=7.87 ignorepadtopadclearanceinfootprint=TRUE
Clearance Clearance_Shunts [InComponentClass('Shunt')] p94: gap=0 ignorepadtopadclearanceinfootprint=TRUE
ComponentClearance ComponentClearance_MountingHoles_FiducialMarks [InComponentClass('Mounting Holes') vs InComponentClass('FiducialMark')] p1: gap=50 collisioncheckmode=3 verticalgap=10 showdistances=FALSE
ComponentClearance ComponentClearance_Shunt [InComponentClass('Shunt') vs InComponentClass('All Components')] p2: gap=0 collisioncheckmode=3 verticalgap=0 showdistances=FALSE
ComponentClearance ComponentClearance_Logo [InComponentClass('Logo')] p3: gap=50 collisioncheckmode=3 verticalgap=10 showdistances=FALSE
ComponentClearance ComponentClearance_ScrewToNut [(HasFootprint('NY PMS 440 0025 PH')) vs (HasFootprint('Keystone_1902C'))] p4: gap=5 collisioncheckmode=3 verticalgap=10 showdistances=FALSE
ComponentClearance ComponentClearance_MountingHoles [InComponentClass('Mounting Holes')] p5: gap=250 collisioncheckmode=3 verticalgap=100000 showdistances=FALSE
ComponentClearance ComponentClearance_SmallPassives [HasFootprint('0201*') or HasFootprint('0402*') or HasFootprint('0508') or HasFootprint('0603*') or HasFootprint('0612') or HasFootprint('0805*') or HasFootprint('0815*') or HasFootprint('0830*') or HasFootprint('1206*') or HasFootprint('1210*') or HasFootprint('1808*') or HasFootprint('1812*') or HasFootprint('1825*') or HasFootprint('2010*') or HasFootprint('2220*') or HasFootprint('2225*') or HasFootprint('2512*') or HasFootprint('2728*') or HasFootprint('3518*') vs HasFootprint('0201*') or HasFootprint('0402*') or HasFootprint('0508') or HasFootprint('0603*') or HasFootprint('0612') or HasFootprint('0805*') or HasFootprint('0815*') or HasFootprint('0830*') or HasFootprint('1206*') or HasFootprint('1210*') or HasFootprint('1808*') or HasFootprint('1812*') or HasFootprint('1825*') or HasFootprint('2010*') or HasFootprint('2220*') or HasFootprint('2225*') or HasFootprint('2512*') or HasFootprint('2728*') or HasFootprint('3518*')] p6: gap=14.96 collisioncheckmode=3 verticalgap=10 showdistances=FALSE
ComponentClearance ComponentClearance_THtoSMT [IsThruComponent vs IsSMTComponent] p7: gap=40 collisioncheckmode=3 verticalgap=30 showdistances=FALSE
ComponentClearance ComponentClearance_THtoTH [IsThruComponent vs IsThruComponent] p8: gap=30 collisioncheckmode=3 verticalgap=30 showdistances=FALSE
ComponentClearance [All] p9: gap=30 collisioncheckmode=3 verticalgap=10 showdistances=FALSE
DiffPairsRouting [All] p1: maxlimit=100 minlimit=10 mostfreqgap=10 toplayer_minwidth=6.3 toplayer_maxwidth=15 toplayer_prefwidth=10 midlayer1_minwidth=15 midlayer1_maxwidth=15 midlayer1_prefwidth=15 midlayer2_minwidth=15 midlayer2_maxwidth=15 midlayer2_prefwidth=15 bottomlayer_minwidth=6.3 bottomlayer_maxwidth=15 bottomlayer_prefwidth=10 maxuncoupledlength=1000
FabricationTestPointUsage TestPointUsage [All] p1: valid=2 allowmultiple=FALSE
FabricationTestpoint Testpoint [All] p1: side=3 testpointundercomponent=TRUE minsize=40 maxsize=100 preferedsize=60 minholesize=0 maxholesize=40 preferedholesize=32 testpointgrid=1 allowsidetop=TRUE allowsidebottom=TRUE usegrid=TRUE gridtolerance=0.01
FanoutControl Fanout_LCC [IsLCC] p1: bgadir=Out bgaviamode=Centered fanoutstyle=Auto fanoutdirection=Alternating viagrid=1 // Fanout_LCC (Default Rule)
FanoutControl Fanout_BGA [IsBGA] p2: bgadir=Out bgaviamode=Centered fanoutstyle=Auto fanoutdirection=Alternating viagrid=1 // Fanout_BGA (Default Rule)
FanoutControl Fanout_Default [All] p4: bgadir=Out bgaviamode=Centered fanoutstyle=Auto fanoutdirection=Alternating viagrid=1 // Fanout_Default (Default Rule)
FanoutControl Fanout_Small [(CompPinCount < 5)] p5: bgadir=Out bgaviamode=Centered fanoutstyle=Auto fanoutdirection=OutThenIn viagrid=1 // Fanout_Small (Default Rule)
HoleSize [All] p1: absolutevalues=TRUE maxlimit=251 minlimit=7.87 maxpercent=80.000 minpercent=20.000
MinimumAnnularRing MinimumAnnularRing_ThermalPadVias [IsVia and InAnyComponent] p1: minimumring=5.91
MinimumAnnularRing [All] p2: minimumring=7.87
MinimumSolderMaskSliver MinimumSolderMaskSliver_Logo [InComponentClass('Logo') vs InComponentClass('Logo')] p1: minsoldermaskwidth=0.7
MinimumSolderMaskSliver [All] p2: minsoldermaskwidth=3.94
PlaneConnect [All] p1: planeconnectstyle=Direct reliefexpansion=10 reliefentries=4 reliefconductorwidth=10 reliefairgap=10
PolygonConnect PolygonConnect_82 [All vs IsNamedPolygon('TOP_LAYER_NONET_P-001')] p1: connectstyle=Direct reliefconductorwidth=10 reliefentries=4 polygonreliefangle="90 Angle" airgapwidth=10
PolygonConnect PolygonConnect_81 [All vs IsNamedPolygon('TOP_LAYER_GND_P227')] p2: connectstyle=Direct reliefconductorwidth=10 reliefentries=4 polygonreliefangle="90 Angle" airgapwidth=10
PolygonConnect PolygonConnect_80 [All vs IsNamedPolygon('TOP_LAYER_GND_P129')] p3: connectstyle=Direct reliefconductorwidth=10 reliefentries=4 polygonreliefangle="90 Angle" airgapwidth=10
PolygonConnect PolygonConnect_79 [All vs IsNamedPolygon('TOP_LAYER_VM_P229')] p4: connectstyle=Direct reliefconductorwidth=10 reliefentries=4 polygonreliefangle="90 Angle" airgapwidth=10
PolygonConnect PolygonConnect_78 [All vs IsNamedPolygon('TOP_LAYER_GND_P129')] p5: connectstyle=Direct reliefconductorwidth=10 reliefentries=4 polygonreliefangle="90 Angle" airgapwidth=10
PolygonConnect PolygonConnect_77 [All vs IsNamedPolygon('TOP_LAYER_OUT1_P221')] p6: connectstyle=Direct reliefconductorwidth=10 reliefentries=4 polygonreliefangle="90 Angle" airgapwidth=10
PolygonConnect PolygonConnect_76 [All vs IsNamedPolygon('TOP_LAYER_OUT1_P119')] p7: connectstyle=Direct reliefconductorwidth=10 reliefentries=4 polygonreliefangle="90 Angle" airgapwidth=10
PolygonConnect PolygonConnect_75 [All vs IsNamedPolygon('TOP_LAYER_OUT1_P119')] p8: connectstyle=Direct reliefconductorwidth=10 reliefentries=4 polygonreliefangle="90 Angle" airgapwidth=10
PolygonConnect PolygonConnect_74 [All vs IsNamedPolygon('TOP_LAYER_OUT1_P119')] p9: connectstyle=Direct reliefconductorwidth=10 reliefentries=4 polygonreliefangle="90 Angle" airgapwidth=10
PolygonConnect PolygonConnect_73 [All vs IsNamedPolygon('TOP_LAYER_OUT1_P221')] p10: connectstyle=Direct reliefconductorwidth=10 reliefentries=4 polygonreliefangle="90 Angle" airgapwidth=10
PolygonConnect PolygonConnect_72 [All vs IsNamedPolygon('TOP_LAYER_GND_P121')] p11: connectstyle=Direct reliefconductorwidth=10 reliefentries=4 polygonreliefangle="90 Angle" airgapwidth=10
PolygonConnect PolygonConnect_71 [All vs IsNamedPolygon('TOP_LAYER_OUT1_P119') Or  IsNamedPolygon('TOP_LAYER_OUT2_P125')] p12: connectstyle=Direct reliefconductorwidth=10 reliefentries=4 polygonreliefangle="90 Angle" airgapwidth=10
PolygonConnect PolygonConnect_70 [All vs IsNamedPolygon('TOP_LAYER_OUT1_P119')] p13: connectstyle=Direct reliefconductorwidth=10 reliefentries=4 polygonreliefangle="90 Angle" airgapwidth=10
PolygonConnect PolygonConnect_69 [All vs IsNamedPolygon('TOP_LAYER_OUT2_P125')] p14: connectstyle=Direct reliefconductorwidth=10 reliefentries=4 polygonreliefangle="90 Angle" airgapwidth=10
PolygonConnect PolygonConnect_68 [All vs IsNamedPolygon('TOP_LAYER_VM_P085')] p15: connectstyle=Direct reliefconductorwidth=10 reliefentries=4 polygonreliefangle="90 Angle" airgapwidth=10
PolygonConnect PolygonConnect_67 [All vs IsNamedPolygon('BOTTOM_LAYER_P_IN_P174')] p16: connectstyle=Direct reliefconductorwidth=10 reliefentries=4 polygonreliefangle="90 Angle" airgapwidth=10
PolygonConnect PolygonConnect_66 [All vs IsNamedPolygon('BOTTOM_LAYER_NETF1_2_P203')] p17: connectstyle=Direct reliefconductorwidth=10 reliefentries=4 polygonreliefangle="90 Angle" airgapwidth=10
PolygonConnect PolygonConnect_65 [All vs IsNamedPolygon('BOTTOM_LAYER_VBAT_P080')] p18: connectstyle=Direct reliefconductorwidth=10 reliefentries=4 polygonreliefangle="90 Angle" airgapwidth=10
PolygonConnect PolygonConnect_64 [All vs IsNamedPolygon('TOP_LAYER_VM_P167')] p19: connectstyle=Direct reliefconductorwidth=10 reliefentries=4 polygonreliefangle="90 Angle" airgapwidth=10
PolygonConnect PolygonConnect_63 [All vs IsNamedPolygon('TOP_LAYER_VM_P167')] p20: connectstyle=Direct reliefconductorwidth=10 reliefentries=4 polygonreliefangle="90 Angle" airgapwidth=10
PolygonConnect PolygonConnect_62 [All vs IsNamedPolygon('TOP_LAYER_VM_P171')] p21: connectstyle=Direct reliefconductorwidth=10 reliefentries=4 polygonreliefangle="90 Angle" airgapwidth=10
PolygonConnect PolygonConnect_61 [All vs IsNamedPolygon('SIGNAL_LAYER_2_GND_P199')] p22: connectstyle=Direct reliefconductorwidth=10 reliefentries=4 polygonreliefangle="90 Angle" airgapwidth=10
PolygonConnect PolygonConnect_60 [All vs IsNamedPolygon('SIGNAL_LAYER_2_NETF1_2_P196')] p23: connectstyle=Direct reliefconductorwidth=10 reliefentries=4 polygonreliefangle="90 Angle" airgapwidth=10
PolygonConnect PolygonConnect_59 [All vs IsNamedPolygon('SIGNAL_LAYER_2_VBAT_P197')] p24: connectstyle=Direct reliefconductorwidth=10 reliefentries=4 polygonreliefangle="90 Angle" airgapwidth=10
PolygonConnect PolygonConnect_58 [All vs IsNamedPolygon('SIGNAL_LAYER_2_P_IN_P198')] p25: connectstyle=Direct reliefconductorwidth=10 reliefentries=4 polygonreliefangle="90 Angle" airgapwidth=10
PolygonConnect PolygonConnect_57 [All vs IsNamedPolygon('SIGNAL_LAYER_2_3V3_P194')] p26: connectstyle=Direct reliefconductorwidth=10 reliefentries=4 polygonreliefangle="90 Angle" airgapwidth=10
PolygonConnect PolygonConnect_56 [All vs IsNamedPolygon('TOP_LAYER_NETF1_2_P223')] p27: connectstyle=Direct reliefconductorwidth=10 reliefentries=4 polygonreliefangle="90 Angle" airgapwidth=10
PolygonConnect PolygonConnect_55 [All vs IsNamedPolygon('TOP_LAYER_VBAT_P201')] p28: connectstyle=Direct reliefconductorwidth=10 reliefentries=4 polygonreliefangle="90 Angle" airgapwidth=10
PolygonConnect PolygonConnect_54 [All vs IsNamedPolygon('TOP_LAYER_P_IN_P207')] p29: connectstyle=Direct reliefconductorwidth=10 reliefentries=4 polygonreliefangle="90 Angle" airgapwidth=10
PolygonConnect PolygonConnect_53 [All vs IsNamedPolygon('TOP_LAYER_GND_P129')] p30: connectstyle=Direct reliefconductorwidth=10 reliefentries=4 polygonreliefangle="90 Angle" airgapwidth=10
PolygonConnect PolygonConnect_52 [All vs IsNamedPolygon('SIGNAL_LAYER_2_VM_P177') Or  IsNamedPolygon('SIGNAL_LAYER_2_VM_P179') Or  IsNamedPolygon('SIGNAL_LAYER_2_VM_P160') Or  IsNamedPolygon('SIGNAL_LAYER_2_VM_P175') Or  IsNamedPolygon('SIGNAL_LAYER_2_VM_P181')] p31: connectstyle=Direct reliefconductorwidth=10 reliefentries=4 polygonreliefangle="90 Angle" airgapwidth=10
PolygonConnect PolygonConnect_51 [All vs IsNamedPolygon('SIGNAL_LAYER_2_EZFET_VBUS_P136')] p32: connectstyle=Direct reliefconductorwidth=10 reliefentries=4 polygonreliefangle="90 Angle" airgapwidth=10
PolygonConnect PolygonConnect_50 [All vs IsNamedPolygon('SIGNAL_LAYER_2_EZFET_VCC_P132')] p33: connectstyle=Direct reliefconductorwidth=10 reliefentries=4 polygonreliefangle="90 Angle" airgapwidth=10
PolygonConnect PolygonConnect_49 [All vs IsNamedPolygon('SIGNAL_LAYER_2_3V3_MCU_P192')] p34: connectstyle=Direct reliefconductorwidth=10 reliefentries=4 polygonreliefangle="90 Angle" airgapwidth=10
PolygonConnect PolygonConnect_48 [All vs IsNamedPolygon('SIGNAL_LAYER_1_GND_P190')] p35: connectstyle=Direct reliefconductorwidth=10 reliefentries=4 polygonreliefangle="90 Angle" airgapwidth=10
PolygonConnect PolygonConnect_47 [All vs IsNamedPolygon('SIGNAL_LAYER_1_GND_P184')] p36: connectstyle=Direct reliefconductorwidth=10 reliefentries=4 polygonreliefangle="90 Angle" airgapwidth=10
PolygonConnect PolygonConnect_46 [All vs IsNamedPolygon('BOTTOM_LAYER_GND_P231')] p37: connectstyle=Direct reliefconductorwidth=10 reliefentries=4 polygonreliefangle="90 Angle" airgapwidth=10
PolygonConnect PolygonConnect_45 [All vs IsNamedPolygon('BOTTOM_LAYER_GND_P231')] p38: connectstyle=Direct reliefconductorwidth=10 reliefentries=4 polygonreliefangle="90 Angle" airgapwidth=10
PolygonConnect PolygonConnect_44 [All vs IsNamedPolygon('BOTTOM_LAYER_OUT2_P163')] p39: connectstyle=Direct reliefconductorwidth=10 reliefentries=4 polygonreliefangle="90 Angle" airgapwidth=10
PolygonConnect PolygonConnect_43 [All vs IsNamedPolygon('BOTTOM_LAYER_VM_P166')] p40: connectstyle=Direct reliefconductorwidth=10 reliefentries=4 polygonreliefangle="90 Angle" airgapwidth=10
PolygonConnect PolygonConnect_42 [All vs IsNamedPolygon('BOTTOM_LAYER_VM_P219')] p41: connectstyle=Direct reliefconductorwidth=10 reliefentries=4 polygonreliefangle="90 Angle" airgapwidth=10
PolygonConnect PolygonConnect_41 [All vs IsNamedPolygon('BOTTOM_LAYER_OUT1_P164')] p42: connectstyle=Direct reliefconductorwidth=10 reliefentries=4 polygonreliefangle="90 Angle" airgapwidth=10
PolygonConnect PolygonConnect_40 [All vs IsNamedPolygon('BOTTOM_LAYER_GND_P162')] p43: connectstyle=Direct reliefconductorwidth=10 reliefentries=4 polygonreliefangle="90 Angle" airgapwidth=10
PolygonConnect PolygonConnect_39 [All vs IsNamedPolygon('SIGNAL_LAYER_2_VM_P160')] p44: connectstyle=Direct reliefconductorwidth=10 reliefentries=4 polygonreliefangle="90 Angle" airgapwidth=10
PolygonConnect PolygonConnect_38 [All vs IsNamedPolygon('SIGNAL_LAYER_2_NONET_P138')] p45: connectstyle=Direct reliefconductorwidth=10 reliefentries=4 polygonreliefangle="90 Angle" airgapwidth=10
PolygonConnect PolygonConnect_37 [All vs IsNamedPolygon('SIGNAL_LAYER_1_VM_P146')] p46: connectstyle=Direct reliefconductorwidth=10 reliefentries=4 polygonreliefangle="90 Angle" airgapwidth=10
PolygonConnect PolygonConnect_36 [All vs IsNamedPolygon('SIGNAL_LAYER_2_GND_P156')] p47: connectstyle=Direct reliefconductorwidth=10 reliefentries=4 polygonreliefangle="90 Angle" airgapwidth=10
PolygonConnect PolygonConnect_35 [All vs IsNamedPolygon('BOTTOM_LAYER_EZFET_USB_SHIELD_P211')] p48: connectstyle=Direct reliefconductorwidth=10 reliefentries=4 polygonreliefangle="90 Angle" airgapwidth=10
PolygonConnect PolygonConnect_34 [All vs IsNamedPolygon('SIGNAL_LAYER_1_VM_P144')] p49: connectstyle=Direct reliefconductorwidth=10 reliefentries=4 polygonreliefangle="90 Angle" airgapwidth=10
PolygonConnect PolygonConnect_33 [All vs IsNamedPolygon('SIGNAL_LAYER_1_VM_P148') Or  IsNamedPolygon('SIGNAL_LAYER_1_VM_P148')] p50: connectstyle=Direct reliefconductorwidth=10 reliefentries=4 polygonreliefangle="90 Angle" airgapwidth=10
PolygonConnect PolygonConnect_32 [All vs IsNamedPolygon('SIGNAL_LAYER_1_GND_P154')] p51: connectstyle=Direct reliefconductorwidth=10 reliefentries=4 polygonreliefangle="90 Angle" airgapwidth=10
PolygonConnect PolygonConnect_31 [All vs IsNamedPolygon('SIGNAL_LAYER_2_NONET_P138')] p52: connectstyle=Direct reliefconductorwidth=10 reliefentries=4 polygonreliefangle="90 Angle" airgapwidth=10
PolygonConnect PolygonConnect_30 [All vs IsNamedPolygon('SIGNAL_LAYER_2_GND_P082')] p53: connectstyle=Direct reliefconductorwidth=10 reliefentries=4 polygonreliefangle="90 Angle" airgapwidth=10
PolygonConnect PolygonConnect_29 [All vs IsNamedPolygon('TOP_LAYER_GND_P076')] p54: connectstyle=Direct reliefconductorwidth=10 reliefentries=4 polygonreliefangle="90 Angle" airgapwidth=10
PolygonConnect PolygonConnect_28 [All vs IsNamedPolygon('TOP_LAYER_GND_P087')] p55: connectstyle=Direct reliefconductorwidth=10 reliefentries=4 polygonreliefangle="90 Angle" airgapwidth=10
PolygonConnect PolygonConnect_27 [All vs IsNamedPolygon('TOP_LAYER_VM_P127') Or  IsNamedPolygon('TOP_LAYER_VM_P085')] p56: connectstyle=Direct reliefconductorwidth=10 reliefentries=4 polygonreliefangle="90 Angle" airgapwidth=10
PolygonConnect PolygonConnect_26 [All vs IsNamedPolygon('TOP_LAYER_GND_P117')] p57: connectstyle=Direct reliefconductorwidth=10 reliefentries=4 polygonreliefangle="90 Angle" airgapwidth=10
PolygonConnect PolygonConnect_25 [All vs IsNamedPolygon('TOP_LAYER_OUT2_P125') Or  IsNamedPolygon('TOP_LAYER_OUT1_P119')] p58: connectstyle=Direct reliefconductorwidth=10 reliefentries=4 polygonreliefangle="90 Angle" airgapwidth=10
PolygonConnect PolygonConnect_24 [All vs IsNamedPolygon('SIGNAL_LAYER_2_NONET_P113')] p59: connectstyle=Direct reliefconductorwidth=10 reliefentries=4 polygonreliefangle="90 Angle" airgapwidth=10
PolygonConnect PolygonConnect_23 [All vs IsNamedPolygon('BOTTOM_LAYER_NONET_P115')] p60: connectstyle=Direct reliefconductorwidth=10 reliefentries=4 polygonreliefangle="90 Angle" airgapwidth=10
PolygonConnect PolygonConnect_22 [All vs IsNamedPolygon('SIGNAL_LAYER_1_NONET_P111')] p61: connectstyle=Direct reliefconductorwidth=10 reliefentries=4 polygonreliefangle="90 Angle" airgapwidth=10
PolygonConnect PolygonConnect_21 [All vs IsNamedPolygon('TOP_LAYER_NONET_P083')] p62: connectstyle=Direct reliefconductorwidth=10 reliefentries=4 polygonreliefangle="90 Angle" airgapwidth=10
PolygonConnect PolygonConnect_20 [All vs IsNamedPolygon('TOP_LAYER_NONET_P105')] p63: connectstyle=Direct reliefconductorwidth=10 reliefentries=4 polygonreliefangle="90 Angle" airgapwidth=10
PolygonConnect PolygonConnect_19 [All vs IsNamedPolygon('TOP_LAYER_OUT2_P107')] p64: connectstyle=Direct reliefconductorwidth=10 reliefentries=4 polygonreliefangle="90 Angle" airgapwidth=10
PolygonConnect PolygonConnect_18 [All vs IsNamedPolygon('TOP_LAYER_NONET_P101')] p65: connectstyle=Direct reliefconductorwidth=10 reliefentries=4 polygonreliefangle="90 Angle" airgapwidth=10
PolygonConnect PolygonConnect_17 [All vs IsNamedPolygon('TOP_LAYER_OUT1_P103')] p66: connectstyle=Direct reliefconductorwidth=10 reliefentries=4 polygonreliefangle="90 Angle" airgapwidth=10
PolygonConnect PolygonConnect_16 [All vs IsNamedPolygon('TOP_LAYER_OUT1_P000')] p67: connectstyle=Direct reliefconductorwidth=10 reliefentries=4 polygonreliefangle="90 Angle" airgapwidth=10
PolygonConnect PolygonConnect_15 [All vs IsNamedPolygon('TOP_LAYER_NONET_P093')] p68: connectstyle=Direct reliefconductorwidth=10 reliefentries=4 polygonreliefangle="90 Angle" airgapwidth=10
PolygonConnect PolygonConnect_14 [All vs IsNamedPolygon('TOP_LAYER_OUT2_P099')] p69: connectstyle=Direct reliefconductorwidth=10 reliefentries=4 polygonreliefangle="90 Angle" airgapwidth=10
PolygonConnect PolygonConnect_13 [All vs IsNamedPolygon('TOP_LAYER_OUT1_P000')] p70: connectstyle=Direct reliefconductorwidth=10 reliefentries=4 polygonreliefangle="90 Angle" airgapwidth=10
PolygonConnect PolygonConnect_12 [All vs IsNamedPolygon('BOTTOM_LAYER_NONET_P079') Or  IsNamedPolygon('SIGNAL_LAYER_2_NONET_P078') Or  IsNamedPolygon('SIGNAL_LAYER_1_NONET_P077') Or  IsNamedPolygon('TOP_LAYER_NONET_P083') Or  IsNamedPolygon('BOTTOM_LAYER_NONET_P072') Or  IsNamedPolygon('SIGNAL_LAYER_2_NONET_P070') Or  IsNamedPolygon('SIGNAL_LAYER_1_NONET_P059') Or  IsNamedPolygon('TOP_LAYER_OUT2_P058') Or  IsNamedPolygon('BOTTOM_LAYER_NONET_P056') Or  IsNamedPolygon('SIGNAL_LAYER_2_NONET_P054') Or  IsNamedPolygon('SIGNAL_LAYER_1_NONET_P052') Or  IsNamedPolygon('TOP_LAYER_OUT1_P050') Or  IsNamedPolygon('BOTTOM_LAYER_VM_P044') Or  IsNamedPolygon('SIGNAL_LAYER_2_VM_P042') Or  IsNamedPolygon('SIGNAL_LAYER_1_VM_P040') Or  IsNamedPolygon('TOP_LAYER_VM_P038') Or  IsNamedPolygon('BOTTOM_LAYER_VM_P036') Or  IsNamedPolygon('SIGNAL_LAYER_2_VM_P018') Or  IsNamedPolygon('SIGNAL_LAYER_1_VM_P016') Or  IsNamedPolygon('TOP_LAYER_VM_P002')] p71: connectstyle=Direct reliefconductorwidth=10 reliefentries=4 polygonreliefangle="90 Angle" airgapwidth=10
PolygonConnect PolygonConnect_11 [All vs IsNamedPolygon('TOP_LAYER_NONET_P089') Or  IsNamedPolygon('TOP_LAYER_NONET_P090')] p72: connectstyle=Direct reliefconductorwidth=10 reliefentries=4 polygonreliefangle="90 Angle" airgapwidth=10
PolygonConnect PolygonConnect_10 [All vs IsNamedPolygon('BOTTOM_LAYER_EZFET_USB_SHIELD_P002') Or  IsNamedPolygon('TOP_LAYER_EZFET_USB_SHIELD_P173') Or  IsNamedPolygon('SIGNAL_LAYER_2_EZFET_VBUS_P018') Or  IsNamedPolygon('SIGNAL_LAYER_2_EZFET_VCC_P016')] p73: connectstyle=Direct reliefconductorwidth=10 reliefentries=4 polygonreliefangle="90 Angle" airgapwidth=10
PolygonConnect PolygonConnect_9 [All vs IsNamedPolygon('TOP_LAYER_VM_P123') Or  IsNamedPolygon('TOP_LAYER_VM_P123') Or  IsNamedPolygon('TOP_LAYER_VM_P123')] p74: connectstyle=Direct reliefconductorwidth=10 reliefentries=4 polygonreliefangle="90 Angle" airgapwidth=10
PolygonConnect PolygonConnect_8 [All vs IsNamedPolygon('TOP_LAYER_NONET_P072')] p75: connectstyle=Direct reliefconductorwidth=10 reliefentries=4 polygonreliefangle="90 Angle" airgapwidth=10
PolygonConnect PolygonConnect_7 [All vs IsNamedPolygon('TOP_LAYER_NONET_P072')] p76: connectstyle=Direct reliefconductorwidth=10 reliefentries=4 polygonreliefangle="90 Angle" airgapwidth=10
PolygonConnect PolygonConnect_6 [All vs IsNamedPolygon('TOP_LAYER_VM_P042')] p77: connectstyle=Direct reliefconductorwidth=10 reliefentries=4 polygonreliefangle="90 Angle" airgapwidth=10
PolygonConnect PolygonConnect_5 [All vs IsNamedPolygon('TOP_LAYER_VM_P044')] p78: connectstyle=Direct reliefconductorwidth=10 reliefentries=4 polygonreliefangle="90 Angle" airgapwidth=10
PolygonConnect PolygonConnect_4 [All vs IsNamedPolygon('TOP_LAYER_VM_P046')] p79: connectstyle=Direct reliefconductorwidth=10 reliefentries=4 polygonreliefangle="90 Angle" airgapwidth=10
PolygonConnect PolygonConnect_3 [All vs IsNamedPolygon('TOP_LAYER_GND_P036') Or  IsNamedPolygon('TOP_LAYER_OUT2_P040') Or  IsNamedPolygon('TOP_LAYER_OUT1_P038')] p80: connectstyle=Direct reliefconductorwidth=10 reliefentries=4 polygonreliefangle="90 Angle" airgapwidth=10
PolygonConnect PolygonConnect_2 [InNet('EZFET_VBUS') vs IsNamedPolygon('TOP_LAYER_EZFET_VBUS_P008')] p81: connectstyle=Direct reliefconductorwidth=10 reliefentries=4 polygonreliefangle="90 Angle" airgapwidth=10
PolygonConnect PolygonConnect_1 [InNetClass('Power-Net') vs IsNamedPolygon('TOP_LAYER_EZFET_USB_SHIELD_P173')] p82: connectstyle=Direct reliefconductorwidth=10 reliefentries=4 polygonreliefangle="90 Angle" airgapwidth=10
PolygonConnect [All] p83: connectstyle=Direct reliefconductorwidth=10 reliefentries=4 polygonreliefangle="90 Angle" airgapwidth=10
RoutingVias ThermalPadVias [IsVia and InAnyComponent] p1: holewidth=7.87 width=19.68 viastyle="Through Hole" minholewidth=7.87 minwidth=19.68 maxholewidth=12.99 maxwidth=23.62
RoutingVias [All] p2: holewidth=16 width=34 viastyle="Through Hole" minholewidth=7.87 minwidth=26 maxholewidth=40 maxwidth=65
SilkToBoardRegionClearance [Not ((IsComment or IsDesignator) And (Hide <> 'False')) and not InRegion(1000,500,4000,800)] p1:
SilkToSilkClearance SilkToSilkClearance_Pb-FreeLogo [(HasFootprint('Pb-Free_Overlay_Medium') OR HasFootprint('Pb-Free_Overlay_Small')) vs (HasFootprint('Pb-Free_Overlay_Medium') OR HasFootprint('Pb-Free_Overlay_Small'))] p1: silktosilkclearance=0
SilkToSilkClearance [All] p2: silktosilkclearance=3.94
SilkToSolderMaskClearance SilkToComponentPadClearance [(IsPad or IsFill or IsRegion) and InAnycomponent] p1: minsilkscreentomaskgap=5 clearancetoexposedcopper=TRUE
SilkToSolderMaskClearance "Silk to Solder Mask Opening" [All] p2: minsilkscreentomaskgap=3.94 clearancetoexposedcopper=FALSE
SolderMaskExpansion [All] p1: expansion=1.97 istentingtop=FALSE
UnRoutedNet [All] p1: checkbadconnections=TRUE
Width [All] p1: maxlimit=100 minlimit=6 preferedwidth=10 checkconnectedcopper=TRUE
14 further rules are at their usual default settings.

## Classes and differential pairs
component class MD094E1_DRV8263-Q1EVM_VQFN: C1 C2 C5 C6 C7 C8 C9 C10 C11 C12 C13 C14 C15 C16 C17 C18 C39 C40 C41 C42 C43 C51 C52 C53 C59 C70 D1 D2 D3 D4 D7 D8 F1 F2 J1 J2 J4 J8 J9 J10 J11 J12 J13 J14 J15 J16 J17 J18 L1 Q1 Q2 R1 R2 R3 R4 R5 R6 R7 R8 R9 R10 R11 R12 R13 R14 R15 R16 R17 R18 R19 R20 R21 R22 R23 R24 R25 R26 R27 R28 R29 R30 R31 R39 R40 R52 R53 R54 R55 R56 R57 R58 R59 R60 R61 R62 R63 R64 R65 R66 R67 R68 R69 R70 R71 R72 R73 S1 SH-J1 SH-J2 SH-J3 SH-J4 SH-J5 SH-J6 SH-J7 SH-J8 SH-J13 SH-J14 SH-J15 SH-J16 SH-J18 SH-J19 SH-J20 SH-J21 SH-J22 SH-J23 SH-J24 TP1 TP3 TP4 TP5 TP6 TP7 TP8 TP9 TP10 TP11 TP12 TP13 TP14 TP15 TP16 U1 U2 U3 U4
component class Shunt: SH-J1 SH-J2 SH-J3 SH-J4 SH-J5 SH-J6 SH-J7 SH-J8 SH-J9 SH-J10 SH-J11 SH-J12 SH-J13 SH-J14 SH-J15 SH-J16 SH-J17 SH-J18 SH-J19 SH-J20 SH-J21 SH-J22 SH-J23 SH-J24
net class Power-Net: 3V3_MCU EZFET_VBUS EZFET_VCC GND
component class Header: J2 J5 J7 J10 J11 J12 J13 J16
component class ezFET: C19 C20 C21 C22 C23 C24 C25 C26 C27 C28 C29 C30 C31 C32 C33 C34 C35 C36 C37 C44 C45 C47 C48 C49 C50 D5 D6 J5 J6 J7 L2 L3 R32 R33 R34 R35 R36 R37 R38 R41 R42 R43 R44 R45 R46 R47 R48 R49 R50 R51 SH-J9 SH-J10 SH-J11 SH-J12 SH-J17 U5 U6 U7 Y1
component class Logo: Logo2
component class FiducialMark: FID1 FID2 FID3
component class AssemblyNote: ZZ1 ZZ2 ZZ3 ZZ4
component class Label: LBL1
differential pair USB_D: +USB_D_P -USB_D_N
differential pair EZFET_D: +EZFET_D_P -EZFET_D_N

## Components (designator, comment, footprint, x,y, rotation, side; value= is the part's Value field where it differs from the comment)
C1 "EEE-2AA100UP" SM_RADIAL_E 2362,1420 r270 top value=10uF
C2 "C3216X7R2A104K160AA" 1206_180 2358.27,965.11 r270 bottom value=0.1uF
C5 "885012105012" 0402 1610,1990 r0 top value=1uF
C6 "C2012X7S2A105K125AB" 0805_HV 1720.99,2933.17 r0 top value=1uF
C7 "885012206120" FP-885012206120_0603-MFG 1716.58,2770.09 r0 top value=100nF
C8 "885012206114" 0603 1717.61,2839.42 r0 top value=0.01uF
C9 "885012209026" WCAP-CSGP_1210_L3.2W2.5H1.6 1640,1740 r180 top
C10 "860040875004" WCAP-ATUL_D10H20 2539.51,2520.41 r180 top
C11 "885012206114" 0603 1720.21,2315.81 r0 top value=0.01uF
C12 "885012206120" FP-885012206120_0603-MFG 1728.36,2240.08 r0 top value=100nF
C13 "C2012X7S2A105K125AB" 0805_HV 1713.9,2160.08 r0 top value=1uF
C14 "06031C102KAT2A" 0603 1721.82,3015.01 r180 top value=1000pF
C15 "06031C102KAT2A" 0603 1730,2090 r180 top value=1000pF
C16 "885012207124" WCAP-CSGP_0805_L2W1.25H0.8_Reflow 1650.4,3512 r180 top
C17 "Capacitor" 0402_065L 787.4,2106.3 r0 top value=4.7uF
C18 "885012206020" 0603L 795.28,2157.48 r0 top value=0.1uF
C19 "C1005X5R1A475M050BC" 0402 884.15,3238.01 r45 top value=4.7uF
C20 "GRM155R61A104KA01D" 0402 813.3,3201.7 r315 top value=0.1uF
